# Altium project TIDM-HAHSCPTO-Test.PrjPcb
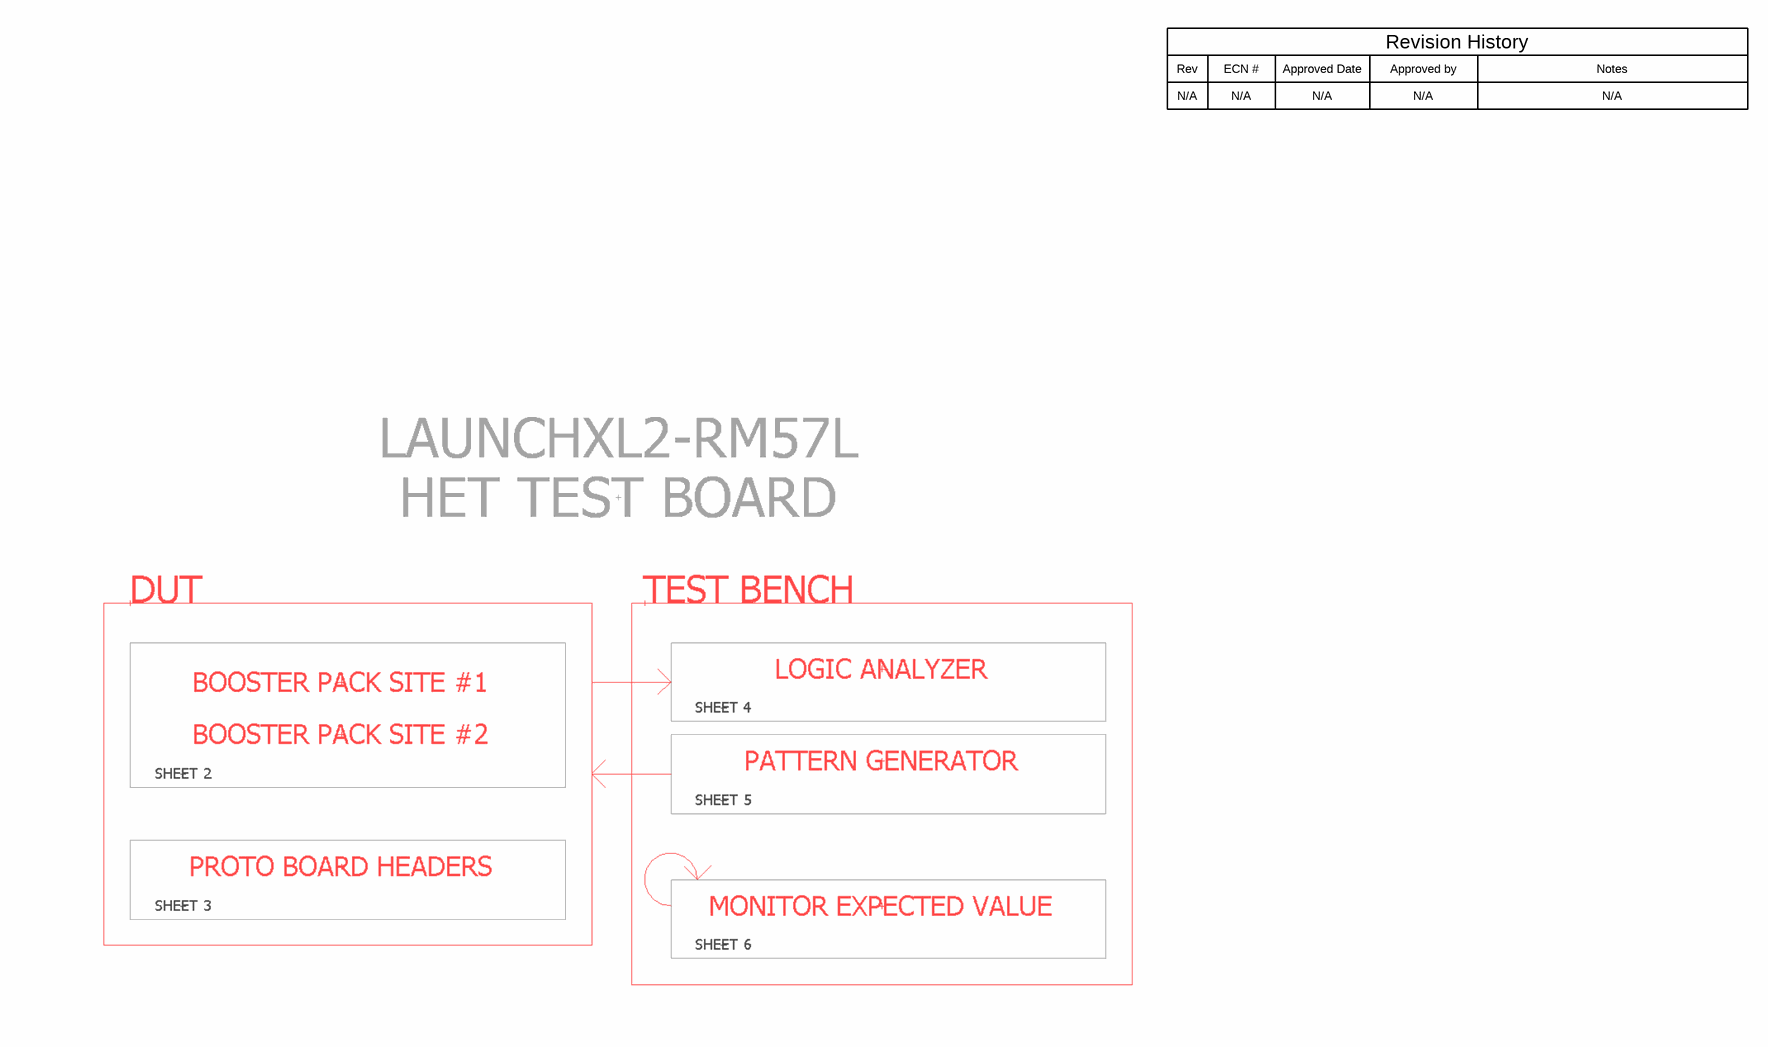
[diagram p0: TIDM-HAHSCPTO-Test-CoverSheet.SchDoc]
TID: TIDM-HAHSCPTO; TechSupport: http://www.ti.com/support; SCH_Rev: A; PRJ_Title: Test Board for TIDM-HAHSCPTO; PRJ_Number: TIDM-HAHSCPTO; PRJ_Engineer: Anthony Seely; PRJ_Customer: Public Release; PCB_Rev: A; PCB_Layout: Anthony Seely; EVM_orderable: n/a; CopyrightYear: 2016
7 sheets, 38 parts. Net scope: flat (ports and power ports of the same name join across sheets).
Board file: TIDM-HAHSCPTO-Test_PCB.PcbDoc
Sheets:
  TIDM-HAHSCPTO-Test-CoverSheet.SchDoc
  TIDM-HAHSCPTO-Test_BoosterPack.SchDoc
  TIDM-HAHSCPTO-Test_Proto.SchDoc
  TIDM-HAHSCPTO-Test_LogicAna.SchDoc
  TIDM-HAHSCPTO-Test_PatGen.SchDoc
  TIDM-HAHSCPTO-Test_Monitor.SchDoc
  TIDM-HAHSCPTO-Test_Hw.SchDoc

## Sheet TIDM-HAHSCPTO-Test-CoverSheet.SchDoc: Block Diagram
size 431 x 279 mm; Date: Not shown in title block; ApprovedBy: Not shown in title block; CheckedBy: Not shown in title block; Author: Not shown in title block; CompanyName: Not shown in title block; DrawnBy: Anthony Seely; Engineer: Anthony Seely; Organization: Not shown in title block; Address1: Not shown in title block; Address2: Not shown in title block; Address3: Not shown in title block; Address4: Not shown in title block; DocumentNumber: 1; Revision: Use project parameter SCH_Rev; SheetNumber: 1; SheetTotal: 3; PageSetup: Record=PageOptions¦CenterHorizontal=True¦CenterVertical=True¦PrintScale=1.00¦XCorrection=1.00¦YCorrection=1.00¦PrintKind=0¦BorderSize=5000000¦LeftOffset=0¦BottomOffset=0¦Orientation=2¦PaperLength=1000¦PaperWidth=1000¦Scale=100¦PaperSource=15¦PrintQuality=600¦MediaType=1¦DitherType=10¦PaperKind=Letter¦PrintScaleMode=1

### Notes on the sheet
- Rev
- N/A
- ECN #
- Approved Date
- Approved by
- Revision History
- Notes

## Sheet TIDM-HAHSCPTO-Test_BoosterPack.SchDoc: Booster Pack
size 431 x 279 mm; Date: Not shown in title block; ApprovedBy: Not shown in title block; CheckedBy: Not shown in title block; Author: Not shown in title block; CompanyName: Not shown in title block; DrawnBy: Anthony Seely; Engineer: Anthony Seely; Organization: Not shown in title block; Address1: Not shown in title block; Address2: Not shown in title block; Address3: Not shown in title block; Address4: Not shown in title block; DocumentNumber: 1; Revision: Use project parameter SCH_Rev; SheetNumber: 2; SheetTotal: 3; PageSetup: Record=PageOptions¦CenterHorizontal=True¦CenterVertical=True¦PrintScale=1.00¦XCorrection=1.00¦YCorrection=1.00¦PrintKind=0¦BorderSize=5000000¦LeftOffset=0¦BottomOffset=0¦Orientation=2¦PaperLength=1000¦PaperWidth=1000¦Scale=100¦PaperSource=15¦PrintQuality=600¦MediaType=1¦DitherType=10¦PaperKind=Letter¦PrintScaleMode=1
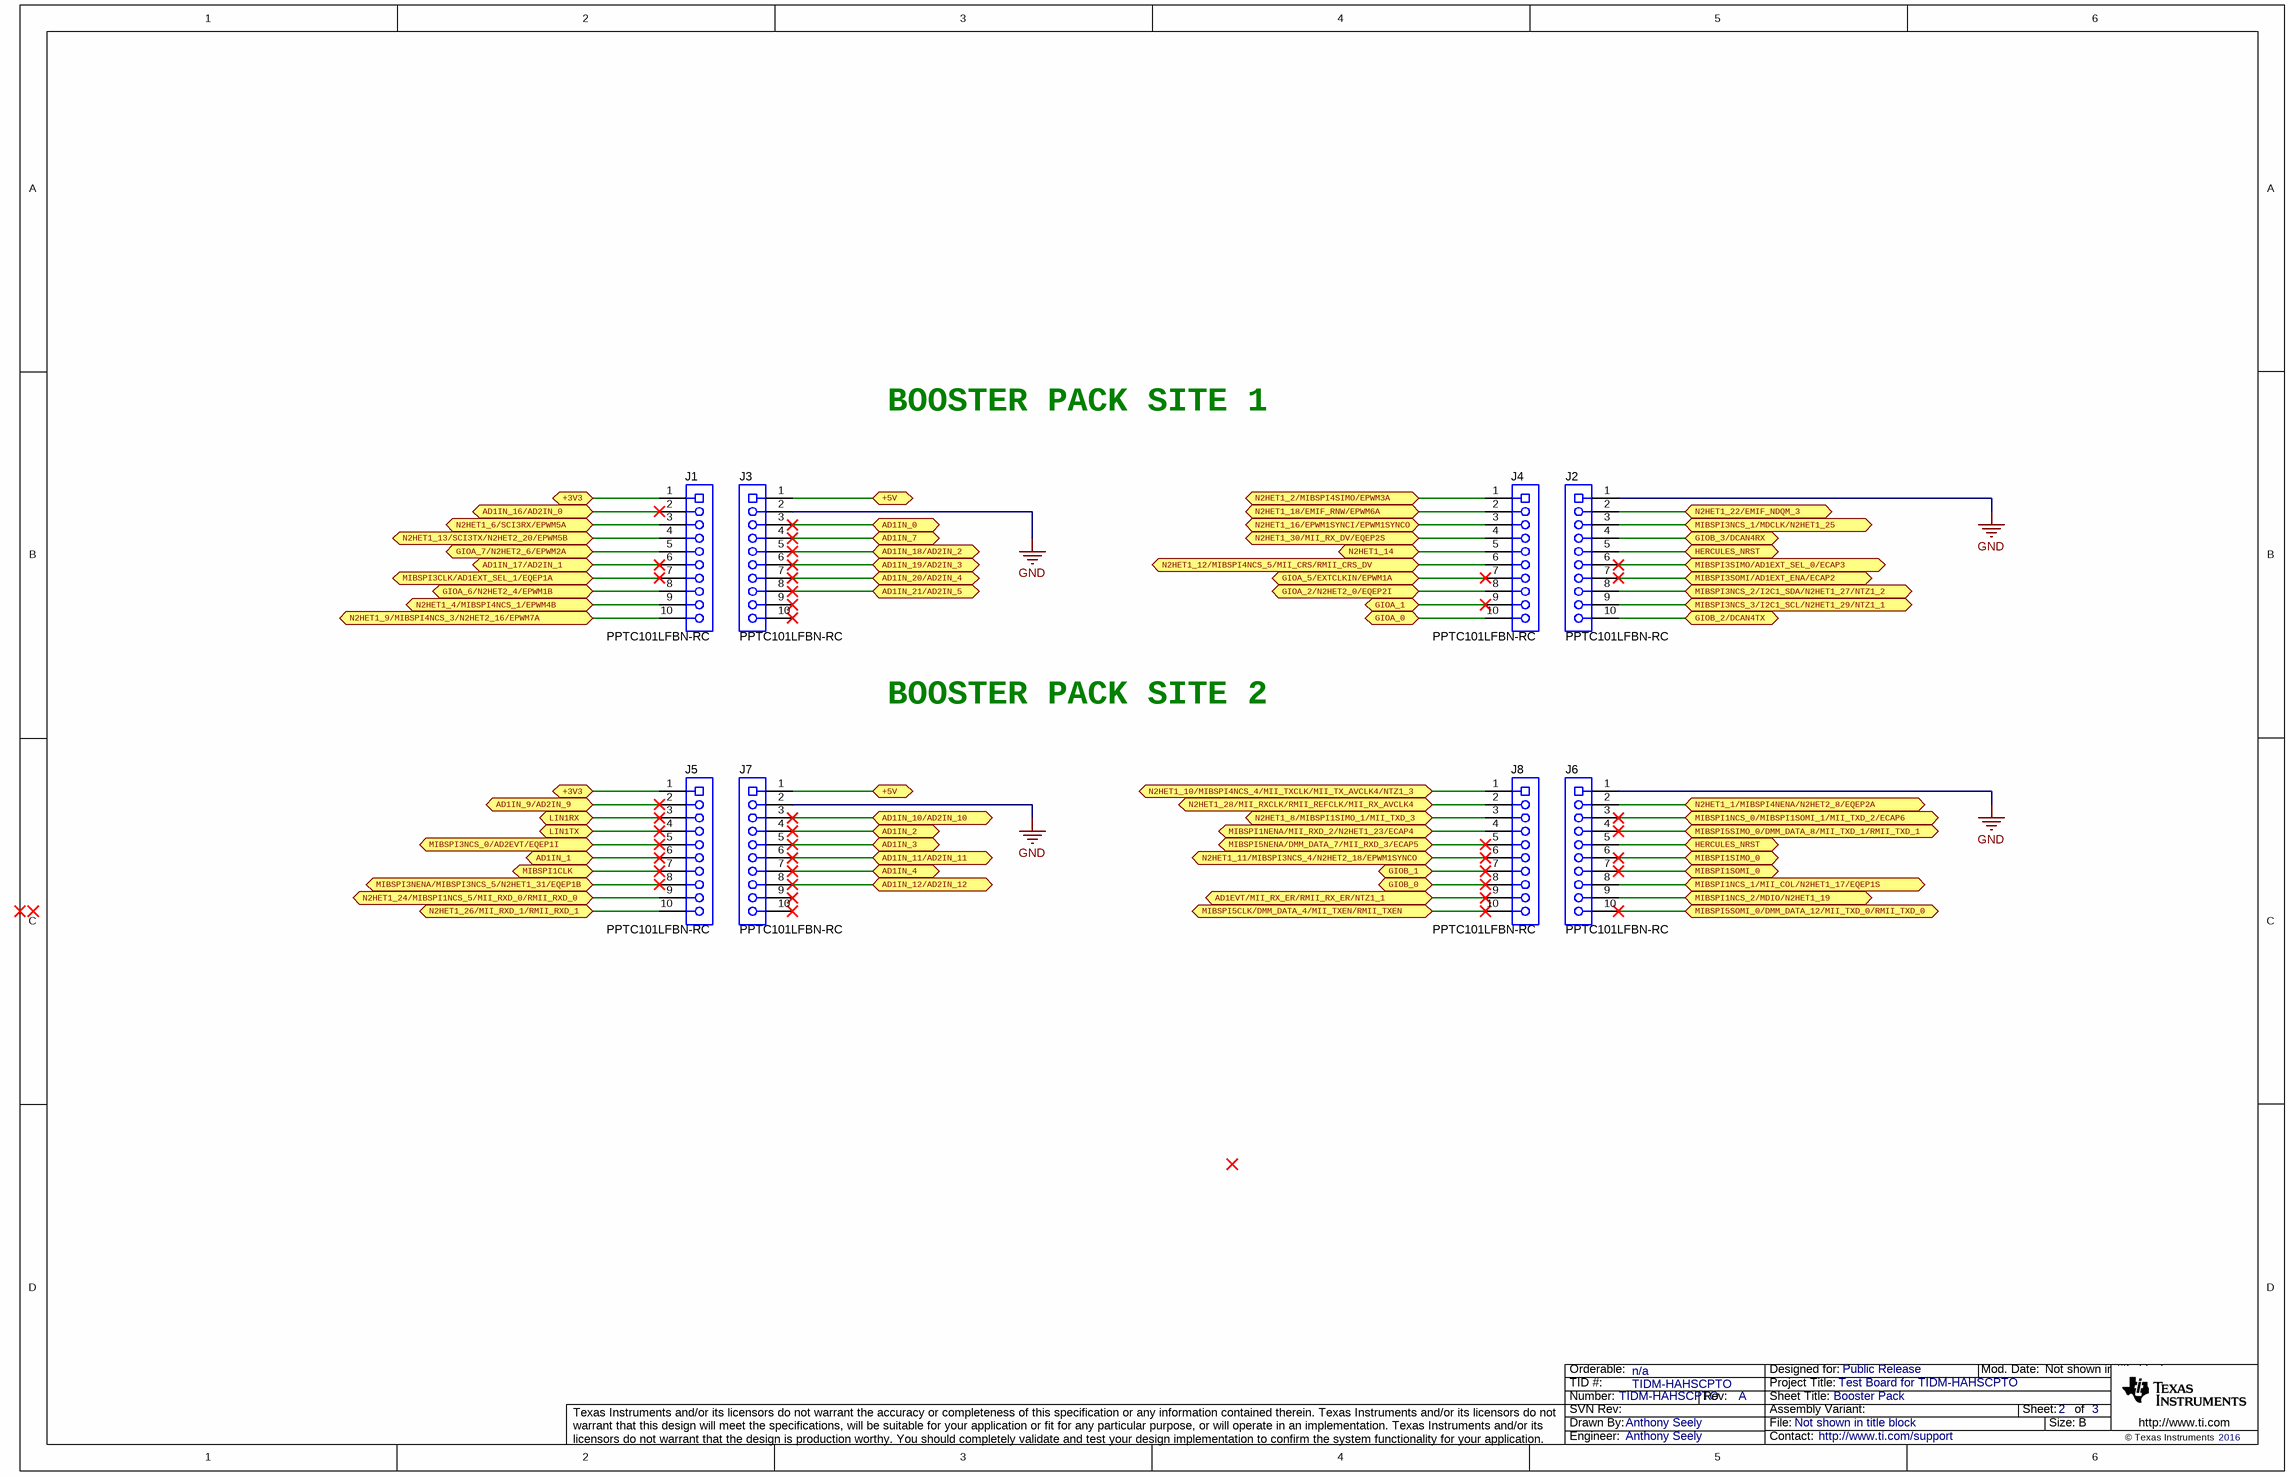
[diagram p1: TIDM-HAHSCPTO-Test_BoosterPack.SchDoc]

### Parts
J1  PPTC101LFBN-RC  [CONN_PPTC101LFBN-RC]
J2  PPTC101LFBN-RC  [CONN_PPTC101LFBN-RC]
J3  PPTC101LFBN-RC  [CONN_PPTC101LFBN-RC]
J4  PPTC101LFBN-RC  [CONN_PPTC101LFBN-RC]
J5  PPTC101LFBN-RC  [CONN_PPTC101LFBN-RC]
J6  PPTC101LFBN-RC  [CONN_PPTC101LFBN-RC]
J7  PPTC101LFBN-RC  [CONN_PPTC101LFBN-RC]
J8  PPTC101LFBN-RC  [CONN_PPTC101LFBN-RC]

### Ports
+3V3, +5V, AD1EVT/MII_RX_ER/RMII_RX_ER/NTZ1_1, AD1IN_0, AD1IN_1, AD1IN_2, AD1IN_3, AD1IN_4, AD1IN_7, AD1IN_9/AD2IN_9, AD1IN_10/AD2IN_10, AD1IN_11/AD2IN_11, AD1IN_12/AD2IN_12, AD1IN_16/AD2IN_0, AD1IN_17/AD2IN_1, AD1IN_18/AD2IN_2, AD1IN_19/AD2IN_3, AD1IN_20/AD2IN_4, AD1IN_21/AD2IN_5, GIOA_0, GIOA_1, GIOA_2/N2HET2_0/EQEP2I, GIOA_5/EXTCLKIN/EPWM1A, GIOA_6/N2HET2_4/EPWM1B, GIOA_7/N2HET2_6/EPWM2A, GIOB_0, GIOB_1, GIOB_2/DCAN4TX, GIOB_3/DCAN4RX, HERCULES_NRST, LIN1RX, LIN1TX, MIBSPI1CLK, MIBSPI1NCS_0/MIBSPI1SOMI_1/MII_TXD_2/ECAP6, MIBSPI1NCS_1/MII_COL/N2HET1_17/EQEP1S, MIBSPI1NCS_2/MDIO/N2HET1_19, MIBSPI1NENA/MII_RXD_2/N2HET1_23/ECAP4, MIBSPI1SIMO_0, MIBSPI1SOMI_0, MIBSPI3CLK/AD1EXT_SEL_1/EQEP1A, MIBSPI3NCS_0/AD2EVT/EQEP1I, MIBSPI3NCS_1/MDCLK/N2HET1_25, MIBSPI3NCS_2/I2C1_SDA/N2HET1_27/NTZ1_2, MIBSPI3NCS_3/I2C1_SCL/N2HET1_29/NTZ1_1, MIBSPI3NENA/MIBSPI3NCS_5/N2HET1_31/EQEP1B, MIBSPI3SIMO/AD1EXT_SEL_0/ECAP3, MIBSPI3SOMI/AD1EXT_ENA/ECAP2, MIBSPI5CLK/DMM_DATA_4/MII_TXEN/RMII_TXEN, MIBSPI5NENA/DMM_DATA_7/MII_RXD_3/ECAP5, MIBSPI5SIMO_0/DMM_DATA_8/MII_TXD_1/RMII_TXD_1, MIBSPI5SOMI_0/DMM_DATA_12/MII_TXD_0/RMII_TXD_0, N2HET1_1/MIBSPI4NENA/N2HET2_8/EQEP2A, N2HET1_2/MIBSPI4SIMO/EPWM3A, N2HET1_4/MIBSPI4NCS_1/EPWM4B, N2HET1_6/SCI3RX/EPWM5A, N2HET1_8/MIBSPI1SIMO_1/MII_TXD_3, N2HET1_9/MIBSPI4NCS_3/N2HET2_16/EPWM7A, N2HET1_10/MIBSPI4NCS_4/MII_TXCLK/MII_TX_AVCLK4/NTZ1_3, N2HET1_11/MIBSPI3NCS_4/N2HET2_18/EPWM1SYNCO, N2HET1_12/MIBSPI4NCS_5/MII_CRS/RMII_CRS_DV, N2HET1_13/SCI3TX/N2HET2_20/EPWM5B, N2HET1_14, N2HET1_16/EPWM1SYNCI/EPWM1SYNCO, N2HET1_18/EMIF_RNW/EPWM6A, N2HET1_22/EMIF_NDQM_3, N2HET1_24/MIBSPI1NCS_5/MII_RXD_0/RMII_RXD_0, N2HET1_26/MII_RXD_1/RMII_RXD_1, N2HET1_28/MII_RXCLK/RMII_REFCLK/MII_RX_AVCLK4, N2HET1_30/MII_RX_DV/EQEP2S

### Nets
GND: J2.1 J3.2 J6.1 J7.2
+3V3: J1.1 J5.1 ; port +3V3
+5V: J3.1 J7.1 ; port +5V
AD1EVT/MII_RX_ER/RMII_RX_ER/NTZ1_1: J8.9 ; port AD1EVT/MII_RX_ER/RMII_RX_ER/NTZ1_1
AD1IN_0: J3.3 ; port AD1IN_0
AD1IN_1: J5.6 ; port AD1IN_1
AD1IN_2: J7.4 ; port AD1IN_2
AD1IN_3: J7.5 ; port AD1IN_3
AD1IN_4: J7.7 ; port AD1IN_4
AD1IN_7: J3.4 ; port AD1IN_7
AD1IN_9/AD2IN_9: J5.2 ; port AD1IN_9/AD2IN_9
AD1IN_10/AD2IN_10: J7.3 ; port AD1IN_10/AD2IN_10
AD1IN_11/AD2IN_11: J7.6 ; port AD1IN_11/AD2IN_11
AD1IN_12/AD2IN_12: J7.8 ; port AD1IN_12/AD2IN_12
AD1IN_16/AD2IN_0: J1.2 ; port AD1IN_16/AD2IN_0
AD1IN_17/AD2IN_1: J1.6 ; port AD1IN_17/AD2IN_1
AD1IN_18/AD2IN_2: J3.5 ; port AD1IN_18/AD2IN_2
AD1IN_19/AD2IN_3: J3.6 ; port AD1IN_19/AD2IN_3
AD1IN_20/AD2IN_4: J3.7 ; port AD1IN_20/AD2IN_4
AD1IN_21/AD2IN_5: J3.8 ; port AD1IN_21/AD2IN_5
GIOA_0: J4.10 ; port GIOA_0
GIOA_1: J4.9 ; port GIOA_1
GIOA_2/N2HET2_0/EQEP2I: J4.8 ; port GIOA_2/N2HET2_0/EQEP2I
GIOA_5/EXTCLKIN/EPWM1A: J4.7 ; port GIOA_5/EXTCLKIN/EPWM1A
GIOA_6/N2HET2_4/EPWM1B: J1.8 ; port GIOA_6/N2HET2_4/EPWM1B
GIOA_7/N2HET2_6/EPWM2A: J1.5 ; port GIOA_7/N2HET2_6/EPWM2A
GIOB_0: J8.8 ; port GIOB_0
GIOB_1: J8.7 ; port GIOB_1
GIOB_2/DCAN4TX: J2.10 ; port GIOB_2/DCAN4TX
GIOB_3/DCAN4RX: J2.4 ; port GIOB_3/DCAN4RX
HERCULES_NRST: J2.5 J6.5 ; port HERCULES_NRST
LIN1RX: J5.3 ; port LIN1RX
LIN1TX: J5.4 ; port LIN1TX
MIBSPI1CLK: J5.7 ; port MIBSPI1CLK
MIBSPI1NCS_0/MIBSPI1SOMI_1/MII_TXD_2/ECAP6: J6.3 ; port MIBSPI1NCS_0/MIBSPI1SOMI_1/MII_TXD_2/ECAP6
MIBSPI1NCS_1/MII_COL/N2HET1_17/EQEP1S: J6.8 ; port MIBSPI1NCS_1/MII_COL/N2HET1_17/EQEP1S
MIBSPI1NCS_2/MDIO/N2HET1_19: J6.9 ; port MIBSPI1NCS_2/MDIO/N2HET1_19
MIBSPI1NENA/MII_RXD_2/N2HET1_23/ECAP4: J8.4 ; port MIBSPI1NENA/MII_RXD_2/N2HET1_23/ECAP4
MIBSPI1SIMO_0: J6.6 ; port MIBSPI1SIMO_0
MIBSPI1SOMI_0: J6.7 ; port MIBSPI1SOMI_0
MIBSPI3CLK/AD1EXT_SEL_1/EQEP1A: J1.7 ; port MIBSPI3CLK/AD1EXT_SEL_1/EQEP1A
MIBSPI3NCS_0/AD2EVT/EQEP1I: J5.5 ; port MIBSPI3NCS_0/AD2EVT/EQEP1I
MIBSPI3NCS_1/MDCLK/N2HET1_25: J2.3 ; port MIBSPI3NCS_1/MDCLK/N2HET1_25
MIBSPI3NCS_2/I2C1_SDA/N2HET1_27/NTZ1_2: J2.8 ; port MIBSPI3NCS_2/I2C1_SDA/N2HET1_27/NTZ1_2
MIBSPI3NCS_3/I2C1_SCL/N2HET1_29/NTZ1_1: J2.9 ; port MIBSPI3NCS_3/I2C1_SCL/N2HET1_29/NTZ1_1
MIBSPI3NENA/MIBSPI3NCS_5/N2HET1_31/EQEP1B: J5.8 ; port MIBSPI3NENA/MIBSPI3NCS_5/N2HET1_31/EQEP1B
MIBSPI3SIMO/AD1EXT_SEL_0/ECAP3: J2.6 ; port MIBSPI3SIMO/AD1EXT_SEL_0/ECAP3
MIBSPI3SOMI/AD1EXT_ENA/ECAP2: J2.7 ; port MIBSPI3SOMI/AD1EXT_ENA/ECAP2
MIBSPI5CLK/DMM_DATA_4/MII_TXEN/RMII_TXEN: J8.10 ; port MIBSPI5CLK/DMM_DATA_4/MII_TXEN/RMII_TXEN
MIBSPI5NENA/DMM_DATA_7/MII_RXD_3/ECAP5: J8.5 ; port MIBSPI5NENA/DMM_DATA_7/MII_RXD_3/ECAP5
MIBSPI5SIMO_0/DMM_DATA_8/MII_TXD_1/RMII_TXD_1: J6.4 ; port MIBSPI5SIMO_0/DMM_DATA_8/MII_TXD_1/RMII_TXD_1
MIBSPI5SOMI_0/DMM_DATA_12/MII_TXD_0/RMII_TXD_0: J6.10 ; port MIBSPI5SOMI_0/DMM_DATA_12/MII_TXD_0/RMII_TXD_0
N2HET1_1/MIBSPI4NENA/N2HET2_8/EQEP2A: J6.2 ; port N2HET1_1/MIBSPI4NENA/N2HET2_8/EQEP2A
N2HET1_2/MIBSPI4SIMO/EPWM3A: J4.1 ; port N2HET1_2/MIBSPI4SIMO/EPWM3A
N2HET1_4/MIBSPI4NCS_1/EPWM4B: J1.9 ; port N2HET1_4/MIBSPI4NCS_1/EPWM4B
N2HET1_6/SCI3RX/EPWM5A: J1.3 ; port N2HET1_6/SCI3RX/EPWM5A
N2HET1_8/MIBSPI1SIMO_1/MII_TXD_3: J8.3 ; port N2HET1_8/MIBSPI1SIMO_1/MII_TXD_3
N2HET1_9/MIBSPI4NCS_3/N2HET2_16/EPWM7A: J1.10 ; port N2HET1_9/MIBSPI4NCS_3/N2HET2_16/EPWM7A
N2HET1_10/MIBSPI4NCS_4/MII_TXCLK/MII_TX_AVCLK4/NTZ1_3: J8.1 ; port N2HET1_10/MIBSPI4NCS_4/MII_TXCLK/MII_TX_AVCLK4/NTZ1_3
N2HET1_11/MIBSPI3NCS_4/N2HET2_18/EPWM1SYNCO: J8.6 ; port N2HET1_11/MIBSPI3NCS_4/N2HET2_18/EPWM1SYNCO
N2HET1_12/MIBSPI4NCS_5/MII_CRS/RMII_CRS_DV: J4.6 ; port N2HET1_12/MIBSPI4NCS_5/MII_CRS/RMII_CRS_DV
N2HET1_13/SCI3TX/N2HET2_20/EPWM5B: J1.4 ; port N2HET1_13/SCI3TX/N2HET2_20/EPWM5B
N2HET1_14: J4.5 ; port N2HET1_14
N2HET1_16/EPWM1SYNCI/EPWM1SYNCO: J4.3 ; port N2HET1_16/EPWM1SYNCI/EPWM1SYNCO
N2HET1_18/EMIF_RNW/EPWM6A: J4.2 ; port N2HET1_18/EMIF_RNW/EPWM6A
N2HET1_22/EMIF_NDQM_3: J2.2 ; port N2HET1_22/EMIF_NDQM_3
N2HET1_24/MIBSPI1NCS_5/MII_RXD_0/RMII_RXD_0: J5.9 ; port N2HET1_24/MIBSPI1NCS_5/MII_RXD_0/RMII_RXD_0
N2HET1_26/MII_RXD_1/RMII_RXD_1: J5.10 ; port N2HET1_26/MII_RXD_1/RMII_RXD_1
N2HET1_28/MII_RXCLK/RMII_REFCLK/MII_RX_AVCLK4: J8.2 ; port N2HET1_28/MII_RXCLK/RMII_REFCLK/MII_RX_AVCLK4
N2HET1_30/MII_RX_DV/EQEP2S: J4.4 ; port N2HET1_30/MII_RX_DV/EQEP2S

Not connected (* = marked no-connect by the designer): J3 9* 10*; J7 9* 10*

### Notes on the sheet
- BOOSTER PACK SITE 1
- BOOSTER PACK SITE 2

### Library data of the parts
J1-J8 = PPTC101LFBN-RC: Receptacle, 100mil, 10x1, Tin, TH; Manufacturer: Sullins Connector Solutions; SymbolCreator: a0411947

## Sheet TIDM-HAHSCPTO-Test_Proto.SchDoc: Prototype Headers
size 431 x 279 mm; Date: Not shown in title block; ApprovedBy: Not shown in title block; CheckedBy: Not shown in title block; Author: Not shown in title block; CompanyName: Not shown in title block; DrawnBy: Anthony Seely; Engineer: Anthony Seely; Organization: Not shown in title block; Address1: Not shown in title block; Address2: Not shown in title block; Address3: Not shown in title block; Address4: Not shown in title block; DocumentNumber: 1; Revision: Use project parameter SCH_Rev; SheetNumber: 2; SheetTotal: 3; PageSetup: Record=PageOptions¦CenterHorizontal=True¦CenterVertical=True¦PrintScale=1.00¦XCorrection=1.00¦YCorrection=1.00¦PrintKind=0¦BorderSize=5000000¦LeftOffset=0¦BottomOffset=0¦Orientation=2¦PaperLength=1000¦PaperWidth=1000¦Scale=100¦PaperSource=15¦PrintQuality=600¦MediaType=1¦DitherType=10¦PaperKind=Letter¦PrintScaleMode=1
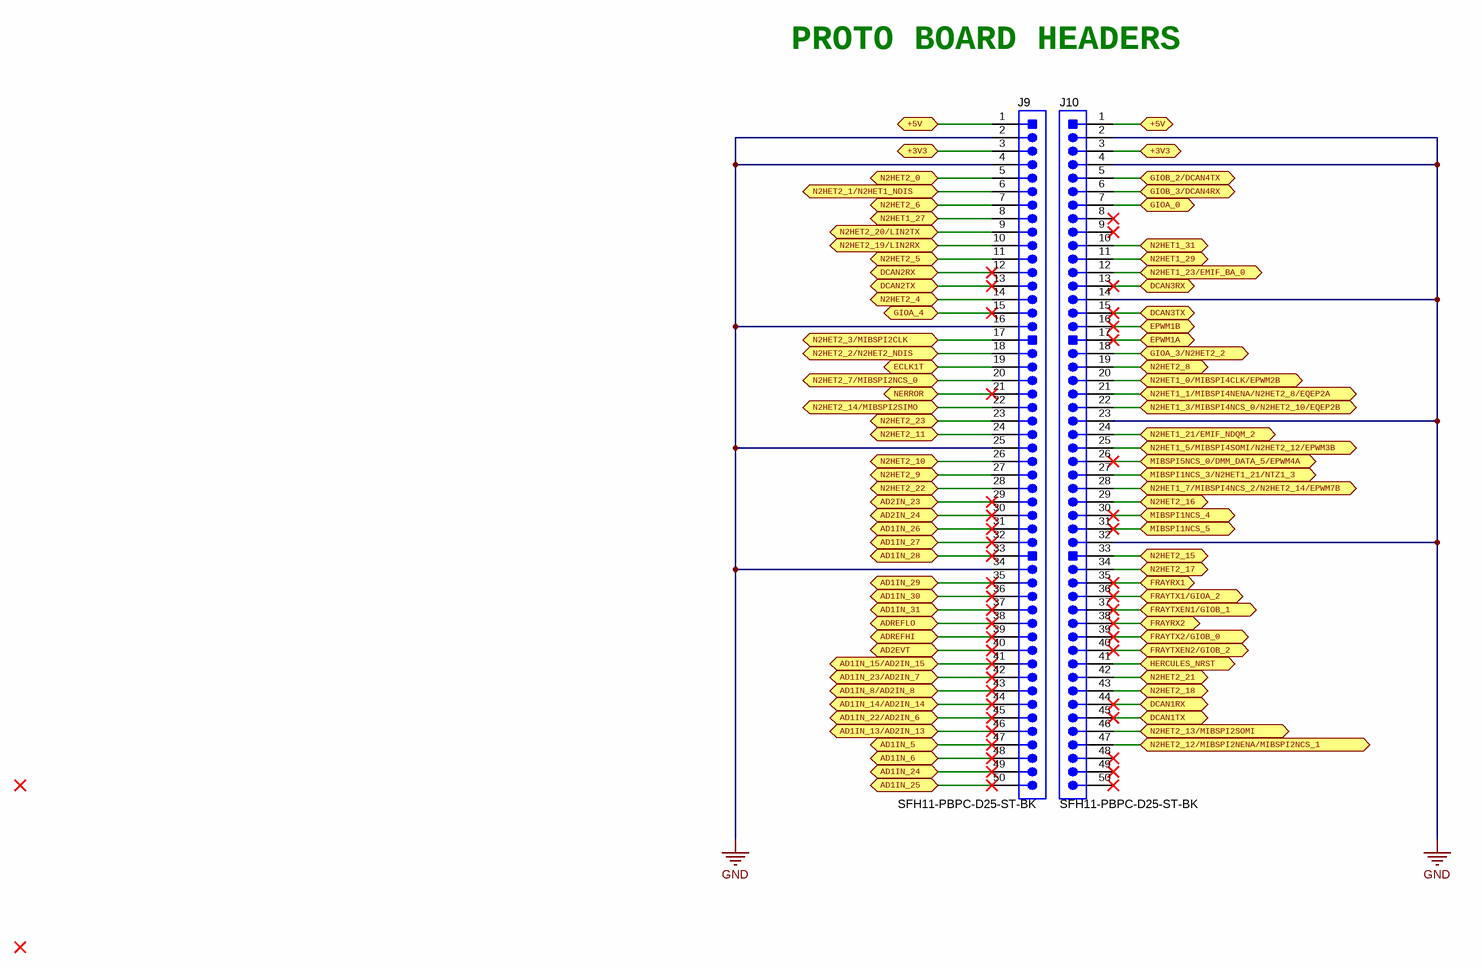
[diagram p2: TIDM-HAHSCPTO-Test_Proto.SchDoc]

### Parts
J9  SFH11-PBPC-D25-ST-BK  [SFH11-PBPC-D25-ST-BK]
J10  SFH11-PBPC-D25-ST-BK  [SFH11-PBPC-D25-ST-BK]

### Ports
+3V3, +5V, AD1IN_5, AD1IN_6, AD1IN_8/AD2IN_8, AD1IN_13/AD2IN_13, AD1IN_14/AD2IN_14, AD1IN_15/AD2IN_15, AD1IN_22/AD2IN_6, AD1IN_23/AD2IN_7, AD1IN_24, AD1IN_25, AD1IN_26, AD1IN_27, AD1IN_28, AD1IN_29, AD1IN_30, AD1IN_31, AD2EVT, AD2IN_23, AD2IN_24, ADREFHI, ADREFLO, DCAN1RX, DCAN1TX, DCAN2RX, DCAN2TX, DCAN3RX, DCAN3TX, ECLK1T, EPWM1A, EPWM1B, FRAYRX1, FRAYRX2, FRAYTX1/GIOA_2, FRAYTX2/GIOB_0, FRAYTXEN1/GIOB_1, FRAYTXEN2/GIOB_2, GIOA_0, GIOA_3/N2HET2_2, GIOA_4, GIOB_2/DCAN4TX, GIOB_3/DCAN4RX, HERCULES_NRST, MIBSPI1NCS_3/N2HET1_21/NTZ1_3, MIBSPI1NCS_4, MIBSPI1NCS_5, MIBSPI5NCS_0/DMM_DATA_5/EPWM4A, N2HET1_0/MIBSPI4CLK/EPWM2B, N2HET1_1/MIBSPI4NENA/N2HET2_8/EQEP2A, N2HET1_3/MIBSPI4NCS_0/N2HET2_10/EQEP2B, N2HET1_5/MIBSPI4SOMI/N2HET2_12/EPWM3B, N2HET1_7/MIBSPI4NCS_2/N2HET2_14/EPWM7B, N2HET1_21/EMIF_NDQM_2, N2HET1_23/EMIF_BA_0, N2HET1_27, N2HET1_29, N2HET1_31, N2HET2_0, N2HET2_1/N2HET1_NDIS, N2HET2_2/N2HET2_NDIS, N2HET2_3/MIBSPI2CLK, N2HET2_4, N2HET2_5, N2HET2_6, N2HET2_7/MIBSPI2NCS_0, N2HET2_8, N2HET2_9, N2HET2_10, N2HET2_11, N2HET2_12/MIBSPI2NENA/MIBSPI2NCS_1, N2HET2_13/MIBSPI2SOMI, N2HET2_14/MIBSPI2SIMO, N2HET2_15, N2HET2_16, N2HET2_17, N2HET2_18, N2HET2_19/LIN2RX, N2HET2_20/LIN2TX, N2HET2_21, N2HET2_22, N2HET2_23, NERROR

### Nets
GND: J9.2 J9.4 J9.16 J9.25 J9.34 J10.2 J10.4 J10.14 J10.23 J10.32
+3V3: J9.3 J10.3 ; port +3V3
+5V: J9.1 J10.1 ; port +5V
AD1IN_5: J9.47 ; port AD1IN_5
AD1IN_6: J9.48 ; port AD1IN_6
AD1IN_8/AD2IN_8: J9.43 ; port AD1IN_8/AD2IN_8
AD1IN_13/AD2IN_13: J9.46 ; port AD1IN_13/AD2IN_13
AD1IN_14/AD2IN_14: J9.44 ; port AD1IN_14/AD2IN_14
AD1IN_15/AD2IN_15: J9.41 ; port AD1IN_15/AD2IN_15
AD1IN_22/AD2IN_6: J9.45 ; port AD1IN_22/AD2IN_6
AD1IN_23/AD2IN_7: J9.42 ; port AD1IN_23/AD2IN_7
AD1IN_24: J9.49 ; port AD1IN_24
AD1IN_25: J9.50 ; port AD1IN_25
AD1IN_26: J9.31 ; port AD1IN_26
AD1IN_27: J9.32 ; port AD1IN_27
AD1IN_28: J9.33 ; port AD1IN_28
AD1IN_29: J9.35 ; port AD1IN_29
AD1IN_30: J9.36 ; port AD1IN_30
AD1IN_31: J9.37 ; port AD1IN_31
AD2EVT: J9.40 ; port AD2EVT
AD2IN_23: J9.29 ; port AD2IN_23
AD2IN_24: J9.30 ; port AD2IN_24
ADREFHI: J9.39 ; port ADREFHI
ADREFLO: J9.38 ; port ADREFLO
DCAN1RX: J10.44 ; port DCAN1RX
DCAN1TX: J10.45 ; port DCAN1TX
DCAN2RX: J9.12 ; port DCAN2RX
DCAN2TX: J9.13 ; port DCAN2TX
DCAN3RX: J10.13 ; port DCAN3RX
DCAN3TX: J10.15 ; port DCAN3TX
ECLK1T: J9.19 ; port ECLK1T
EPWM1A: J10.17 ; port EPWM1A
EPWM1B: J10.16 ; port EPWM1B
FRAYRX1: J10.35 ; port FRAYRX1
FRAYRX2: J10.38 ; port FRAYRX2
FRAYTX1/GIOA_2: J10.36 ; port FRAYTX1/GIOA_2
FRAYTX2/GIOB_0: J10.39 ; port FRAYTX2/GIOB_0
FRAYTXEN1/GIOB_1: J10.37 ; port FRAYTXEN1/GIOB_1
FRAYTXEN2/GIOB_2: J10.40 ; port FRAYTXEN2/GIOB_2
GIOA_0: J10.7 ; port GIOA_0
GIOA_3/N2HET2_2: J10.18 ; port GIOA_3/N2HET2_2
GIOA_4: J9.15 ; port GIOA_4
GIOB_2/DCAN4TX: J10.5 ; port GIOB_2/DCAN4TX
GIOB_3/DCAN4RX: J10.6 ; port GIOB_3/DCAN4RX
HERCULES_NRST: J10.41 ; port HERCULES_NRST
MIBSPI1NCS_3/N2HET1_21/NTZ1_3: J10.27 ; port MIBSPI1NCS_3/N2HET1_21/NTZ1_3
MIBSPI1NCS_4: J10.30 ; port MIBSPI1NCS_4
MIBSPI1NCS_5: J10.31 ; port MIBSPI1NCS_5
MIBSPI5NCS_0/DMM_DATA_5/EPWM4A: J10.26 ; port MIBSPI5NCS_0/DMM_DATA_5/EPWM4A
N2HET1_0/MIBSPI4CLK/EPWM2B: J10.20 ; port N2HET1_0/MIBSPI4CLK/EPWM2B
N2HET1_1/MIBSPI4NENA/N2HET2_8/EQEP2A: J10.21 ; port N2HET1_1/MIBSPI4NENA/N2HET2_8/EQEP2A
N2HET1_3/MIBSPI4NCS_0/N2HET2_10/EQEP2B: J10.22 ; port N2HET1_3/MIBSPI4NCS_0/N2HET2_10/EQEP2B
N2HET1_5/MIBSPI4SOMI/N2HET2_12/EPWM3B: J10.25 ; port N2HET1_5/MIBSPI4SOMI/N2HET2_12/EPWM3B
N2HET1_7/MIBSPI4NCS_2/N2HET2_14/EPWM7B: J10.28 ; port N2HET1_7/MIBSPI4NCS_2/N2HET2_14/EPWM7B
N2HET1_21/EMIF_NDQM_2: J10.24 ; port N2HET1_21/EMIF_NDQM_2
N2HET1_23/EMIF_BA_0: J10.12 ; port N2HET1_23/EMIF_BA_0
N2HET1_27: J9.8 ; port N2HET1_27
N2HET1_29: J10.11 ; port N2HET1_29
N2HET1_31: J10.10 ; port N2HET1_31
N2HET2_0: J9.5 ; port N2HET2_0
N2HET2_1/N2HET1_NDIS: J9.6 ; port N2HET2_1/N2HET1_NDIS
N2HET2_2/N2HET2_NDIS: J9.18 ; port N2HET2_2/N2HET2_NDIS
N2HET2_3/MIBSPI2CLK: J9.17 ; port N2HET2_3/MIBSPI2CLK
N2HET2_4: J9.14 ; port N2HET2_4
N2HET2_5: J9.11 ; port N2HET2_5
N2HET2_6: J9.7 ; port N2HET2_6
N2HET2_7/MIBSPI2NCS_0: J9.20 ; port N2HET2_7/MIBSPI2NCS_0
N2HET2_8: J10.19 ; port N2HET2_8
N2HET2_9: J9.27 ; port N2HET2_9
N2HET2_10: J9.26 ; port N2HET2_10
N2HET2_11: J9.24 ; port N2HET2_11
N2HET2_12/MIBSPI2NENA/MIBSPI2NCS_1: J10.47 ; port N2HET2_12/MIBSPI2NENA/MIBSPI2NCS_1
N2HET2_13/MIBSPI2SOMI: J10.46 ; port N2HET2_13/MIBSPI2SOMI
N2HET2_14/MIBSPI2SIMO: J9.22 ; port N2HET2_14/MIBSPI2SIMO
N2HET2_15: J10.33 ; port N2HET2_15
N2HET2_16: J10.29 ; port N2HET2_16
N2HET2_17: J10.34 ; port N2HET2_17
N2HET2_18: J10.43 ; port N2HET2_18
N2HET2_19/LIN2RX: J9.10 ; port N2HET2_19/LIN2RX
N2HET2_20/LIN2TX: J9.9 ; port N2HET2_20/LIN2TX
N2HET2_21: J10.42 ; port N2HET2_21
N2HET2_22: J9.28 ; port N2HET2_22
N2HET2_23: J9.23 ; port N2HET2_23
NERROR: J9.21 ; port NERROR

Not connected (* = marked no-connect by the designer): J10 8* 9* 48* 49* 50*

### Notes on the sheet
- PROTO BOARD HEADERS

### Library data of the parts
J9 J10 = SFH11-PBPC-D25-ST-BK: .100" 1 Row, Thru Hole with Polarizing Key; Manufacturer: Sullins; SymbolCreator: a0321811; CompType: Connector

## Sheet TIDM-HAHSCPTO-Test_LogicAna.SchDoc: Logic Analyzer Headers
size 431 x 279 mm; Date: Not shown in title block; ApprovedBy: Not shown in title block; CheckedBy: Not shown in title block; Author: Not shown in title block; CompanyName: Not shown in title block; DrawnBy: Anthony  Seely; Engineer: Anthony Seely; Organization: Not shown in title block; Address1: Not shown in title block; Address2: Not shown in title block; Address3: Not shown in title block; Address4: Not shown in title block; DocumentNumber: 1; Revision: Use project parameter SCH_Rev; SheetNumber: 2; SheetTotal: 3; PageSetup: Record=PageOptions¦CenterHorizontal=True¦CenterVertical=True¦PrintScale=1.00¦XCorrection=1.00¦YCorrection=1.00¦PrintKind=0¦BorderSize=5000000¦LeftOffset=0¦BottomOffset=0¦Orientation=2¦PaperLength=1000¦PaperWidth=1000¦Scale=100¦PaperSource=15¦PrintQuality=600¦MediaType=1¦DitherType=10¦PaperKind=Letter¦PrintScaleMode=1
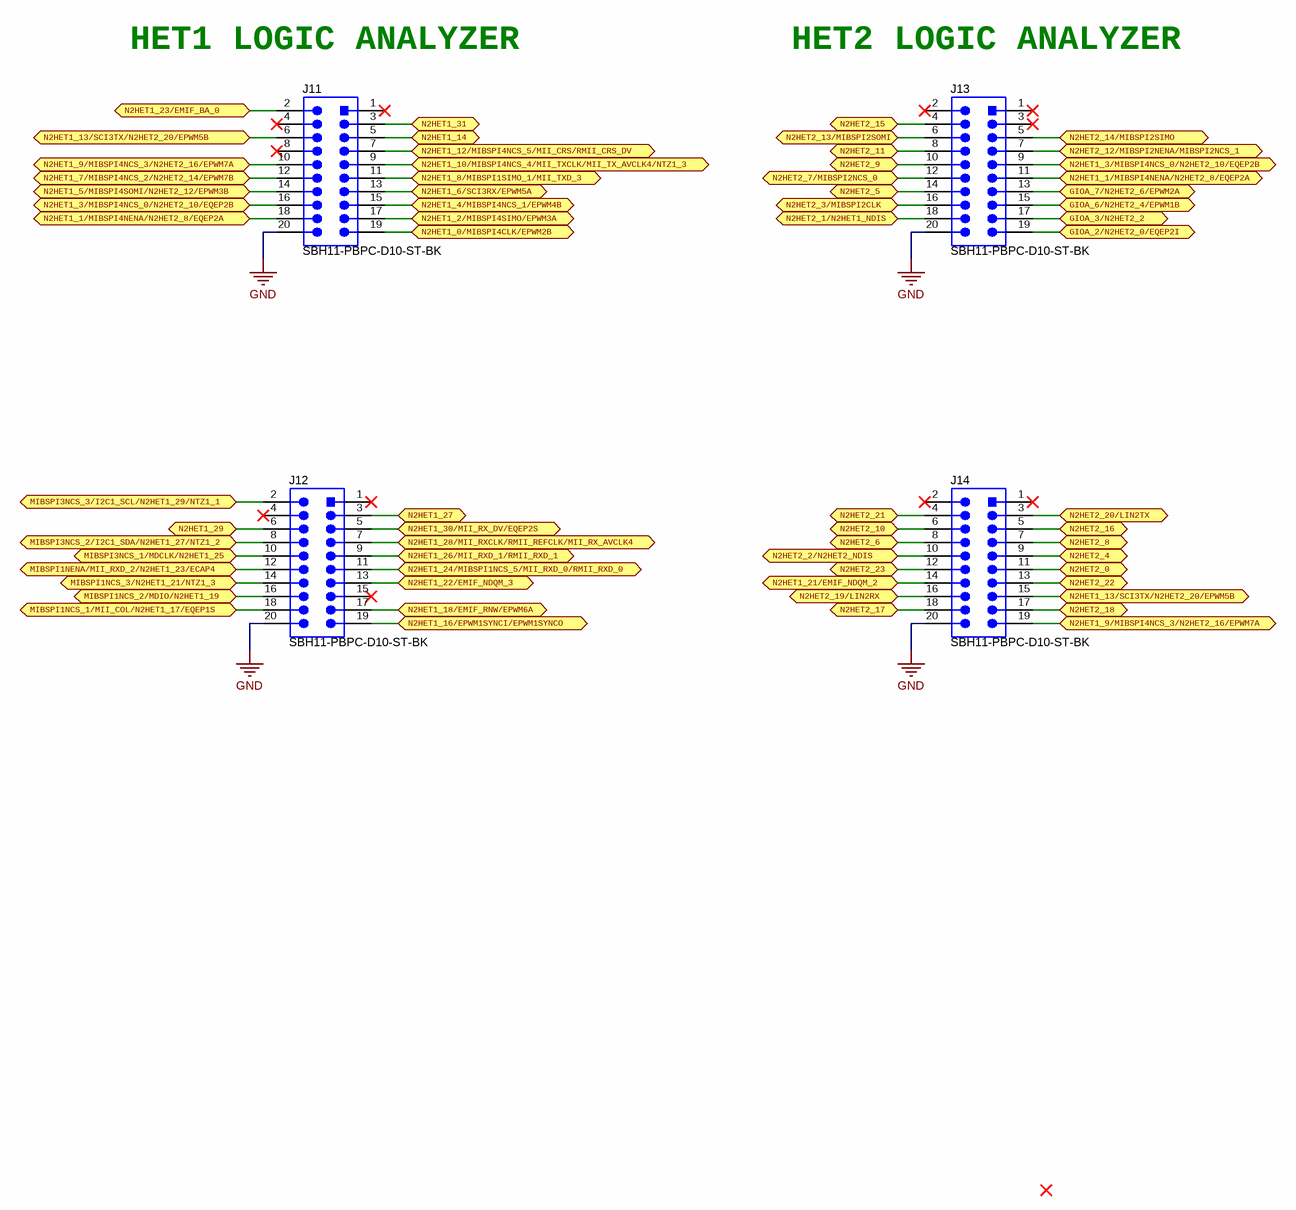
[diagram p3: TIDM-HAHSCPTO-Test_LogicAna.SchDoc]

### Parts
J11  SBH11-PBPC-D10-ST-BK  [Sullins_SBH11-xxxC-D10-ST]
J12  SBH11-PBPC-D10-ST-BK  [Sullins_SBH11-xxxC-D10-ST]
J13  SBH11-PBPC-D10-ST-BK  [Sullins_SBH11-xxxC-D10-ST]
J14  SBH11-PBPC-D10-ST-BK  [Sullins_SBH11-xxxC-D10-ST]

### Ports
GIOA_2/N2HET2_0/EQEP2I, GIOA_3/N2HET2_2, GIOA_6/N2HET2_4/EPWM1B, GIOA_7/N2HET2_6/EPWM2A, MIBSPI1NCS_1/MII_COL/N2HET1_17/EQEP1S, MIBSPI1NCS_2/MDIO/N2HET1_19, MIBSPI1NCS_3/N2HET1_21/NTZ1_3, MIBSPI1NENA/MII_RXD_2/N2HET1_23/ECAP4, MIBSPI3NCS_1/MDCLK/N2HET1_25, MIBSPI3NCS_2/I2C1_SDA/N2HET1_27/NTZ1_2, MIBSPI3NCS_3/I2C1_SCL/N2HET1_29/NTZ1_1, N2HET1_0/MIBSPI4CLK/EPWM2B, N2HET1_1/MIBSPI4NENA/N2HET2_8/EQEP2A, N2HET1_2/MIBSPI4SIMO/EPWM3A, N2HET1_3/MIBSPI4NCS_0/N2HET2_10/EQEP2B, N2HET1_4/MIBSPI4NCS_1/EPWM4B, N2HET1_5/MIBSPI4SOMI/N2HET2_12/EPWM3B, N2HET1_6/SCI3RX/EPWM5A, N2HET1_7/MIBSPI4NCS_2/N2HET2_14/EPWM7B, N2HET1_8/MIBSPI1SIMO_1/MII_TXD_3, N2HET1_9/MIBSPI4NCS_3/N2HET2_16/EPWM7A, N2HET1_10/MIBSPI4NCS_4/MII_TXCLK/MII_TX_AVCLK4/NTZ1_3, N2HET1_12/MIBSPI4NCS_5/MII_CRS/RMII_CRS_DV, N2HET1_13/SCI3TX/N2HET2_20/EPWM5B, N2HET1_14, N2HET1_16/EPWM1SYNCI/EPWM1SYNCO, N2HET1_18/EMIF_RNW/EPWM6A, N2HET1_21/EMIF_NDQM_2, N2HET1_22/EMIF_NDQM_3, N2HET1_23/EMIF_BA_0, N2HET1_24/MIBSPI1NCS_5/MII_RXD_0/RMII_RXD_0, N2HET1_26/MII_RXD_1/RMII_RXD_1, N2HET1_27, N2HET1_28/MII_RXCLK/RMII_REFCLK/MII_RX_AVCLK4, N2HET1_29, N2HET1_30/MII_RX_DV/EQEP2S, N2HET1_31, N2HET2_0, N2HET2_1/N2HET1_NDIS, N2HET2_2/N2HET2_NDIS, N2HET2_3/MIBSPI2CLK, N2HET2_4, N2HET2_5, N2HET2_6, N2HET2_7/MIBSPI2NCS_0, N2HET2_8, N2HET2_9, N2HET2_10, N2HET2_11, N2HET2_12/MIBSPI2NENA/MIBSPI2NCS_1, N2HET2_13/MIBSPI2SOMI, N2HET2_14/MIBSPI2SIMO, N2HET2_15, N2HET2_16, N2HET2_17, N2HET2_18, N2HET2_19/LIN2RX, N2HET2_20/LIN2TX, N2HET2_21, N2HET2_22, N2HET2_23

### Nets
GND: J11.20 J12.20 J13.20 J14.20
GIOA_2/N2HET2_0/EQEP2I: J13.19 ; port GIOA_2/N2HET2_0/EQEP2I
GIOA_3/N2HET2_2: J13.17 ; port GIOA_3/N2HET2_2
GIOA_6/N2HET2_4/EPWM1B: J13.15 ; port GIOA_6/N2HET2_4/EPWM1B
GIOA_7/N2HET2_6/EPWM2A: J13.13 ; port GIOA_7/N2HET2_6/EPWM2A
MIBSPI1NCS_1/MII_COL/N2HET1_17/EQEP1S: J12.18 ; port MIBSPI1NCS_1/MII_COL/N2HET1_17/EQEP1S
MIBSPI1NCS_2/MDIO/N2HET1_19: J12.16 ; port MIBSPI1NCS_2/MDIO/N2HET1_19
MIBSPI1NCS_3/N2HET1_21/NTZ1_3: J12.14 ; port MIBSPI1NCS_3/N2HET1_21/NTZ1_3
MIBSPI1NENA/MII_RXD_2/N2HET1_23/ECAP4: J12.12 ; port MIBSPI1NENA/MII_RXD_2/N2HET1_23/ECAP4
MIBSPI3NCS_1/MDCLK/N2HET1_25: J12.10 ; port MIBSPI3NCS_1/MDCLK/N2HET1_25
MIBSPI3NCS_2/I2C1_SDA/N2HET1_27/NTZ1_2: J12.8 ; port MIBSPI3NCS_2/I2C1_SDA/N2HET1_27/NTZ1_2
MIBSPI3NCS_3/I2C1_SCL/N2HET1_29/NTZ1_1: J12.2 ; port MIBSPI3NCS_3/I2C1_SCL/N2HET1_29/NTZ1_1
N2HET1_0/MIBSPI4CLK/EPWM2B: J11.19 ; port N2HET1_0/MIBSPI4CLK/EPWM2B
N2HET1_1/MIBSPI4NENA/N2HET2_8/EQEP2A: J11.18 J13.11 ; port N2HET1_1/MIBSPI4NENA/N2HET2_8/EQEP2A
N2HET1_2/MIBSPI4SIMO/EPWM3A: J11.17 ; port N2HET1_2/MIBSPI4SIMO/EPWM3A
N2HET1_3/MIBSPI4NCS_0/N2HET2_10/EQEP2B: J11.16 J13.9 ; port N2HET1_3/MIBSPI4NCS_0/N2HET2_10/EQEP2B
N2HET1_4/MIBSPI4NCS_1/EPWM4B: J11.15 ; port N2HET1_4/MIBSPI4NCS_1/EPWM4B
N2HET1_5/MIBSPI4SOMI/N2HET2_12/EPWM3B: J11.14 ; port N2HET1_5/MIBSPI4SOMI/N2HET2_12/EPWM3B
N2HET1_6/SCI3RX/EPWM5A: J11.13 ; port N2HET1_6/SCI3RX/EPWM5A
N2HET1_7/MIBSPI4NCS_2/N2HET2_14/EPWM7B: J11.12 ; port N2HET1_7/MIBSPI4NCS_2/N2HET2_14/EPWM7B
N2HET1_8/MIBSPI1SIMO_1/MII_TXD_3: J11.11 ; port N2HET1_8/MIBSPI1SIMO_1/MII_TXD_3
N2HET1_9/MIBSPI4NCS_3/N2HET2_16/EPWM7A: J11.10 J14.19 ; port N2HET1_9/MIBSPI4NCS_3/N2HET2_16/EPWM7A
N2HET1_10/MIBSPI4NCS_4/MII_TXCLK/MII_TX_AVCLK4/NTZ1_3: J11.9 ; port N2HET1_10/MIBSPI4NCS_4/MII_TXCLK/MII_TX_AVCLK4/NTZ1_3
N2HET1_12/MIBSPI4NCS_5/MII_CRS/RMII_CRS_DV: J11.7 ; port N2HET1_12/MIBSPI4NCS_5/MII_CRS/RMII_CRS_DV
N2HET1_13/SCI3TX/N2HET2_20/EPWM5B: J11.6 J14.15 ; port N2HET1_13/SCI3TX/N2HET2_20/EPWM5B
N2HET1_14: J11.5 ; port N2HET1_14
N2HET1_16/EPWM1SYNCI/EPWM1SYNCO: J12.19 ; port N2HET1_16/EPWM1SYNCI/EPWM1SYNCO
N2HET1_18/EMIF_RNW/EPWM6A: J12.17 ; port N2HET1_18/EMIF_RNW/EPWM6A
N2HET1_21/EMIF_NDQM_2: J14.14 ; port N2HET1_21/EMIF_NDQM_2
N2HET1_22/EMIF_NDQM_3: J12.13 ; port N2HET1_22/EMIF_NDQM_3
N2HET1_23/EMIF_BA_0: J11.2 ; port N2HET1_23/EMIF_BA_0
N2HET1_24/MIBSPI1NCS_5/MII_RXD_0/RMII_RXD_0: J12.11 ; port N2HET1_24/MIBSPI1NCS_5/MII_RXD_0/RMII_RXD_0
N2HET1_26/MII_RXD_1/RMII_RXD_1: J12.9 ; port N2HET1_26/MII_RXD_1/RMII_RXD_1
N2HET1_27: J12.3 ; port N2HET1_27
N2HET1_28/MII_RXCLK/RMII_REFCLK/MII_RX_AVCLK4: J12.7 ; port N2HET1_28/MII_RXCLK/RMII_REFCLK/MII_RX_AVCLK4
N2HET1_29: J12.6 ; port N2HET1_29
N2HET1_30/MII_RX_DV/EQEP2S: J12.5 ; port N2HET1_30/MII_RX_DV/EQEP2S
N2HET1_31: J11.3 ; port N2HET1_31
N2HET2_0: J14.11 ; port N2HET2_0
N2HET2_1/N2HET1_NDIS: J13.18 ; port N2HET2_1/N2HET1_NDIS
N2HET2_2/N2HET2_NDIS: J14.10 ; port N2HET2_2/N2HET2_NDIS
N2HET2_3/MIBSPI2CLK: J13.16 ; port N2HET2_3/MIBSPI2CLK
N2HET2_4: J14.9 ; port N2HET2_4
N2HET2_5: J13.14 ; port N2HET2_5
N2HET2_6: J14.8 ; port N2HET2_6
N2HET2_7/MIBSPI2NCS_0: J13.12 ; port N2HET2_7/MIBSPI2NCS_0
N2HET2_8: J14.7 ; port N2HET2_8
N2HET2_9: J13.10 ; port N2HET2_9
N2HET2_10: J14.6 ; port N2HET2_10
N2HET2_11: J13.8 ; port N2HET2_11
N2HET2_12/MIBSPI2NENA/MIBSPI2NCS_1: J13.7 ; port N2HET2_12/MIBSPI2NENA/MIBSPI2NCS_1
N2HET2_13/MIBSPI2SOMI: J13.6 ; port N2HET2_13/MIBSPI2SOMI
N2HET2_14/MIBSPI2SIMO: J13.5 ; port N2HET2_14/MIBSPI2SIMO
N2HET2_15: J13.4 ; port N2HET2_15
N2HET2_16: J14.5 ; port N2HET2_16
N2HET2_17: J14.18 ; port N2HET2_17
N2HET2_18: J14.17 ; port N2HET2_18
N2HET2_19/LIN2RX: J14.16 ; port N2HET2_19/LIN2RX
N2HET2_20/LIN2TX: J14.3 ; port N2HET2_20/LIN2TX
N2HET2_21: J14.4 ; port N2HET2_21
N2HET2_22: J14.13 ; port N2HET2_22
N2HET2_23: J14.12 ; port N2HET2_23

Not connected (* = marked no-connect by the designer): J11 1* 4* 8*; J12 1* 4* 15*; J13 1* 2* 3*; J14 1* 2*

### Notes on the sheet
- (near J11) HET1 LOGIC ANALYZER
- (near J13) HET2 LOGIC ANALYZER

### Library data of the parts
J11-J14 = SBH11-PBPC-D10-ST-BK: Header (Shrouded), 2.54mm, 10x2, Gold, Black, TH; Manufacturer: Sullins Connector Solutions; SymbolCreator: a0412235; Pitch_mm: 2.54; Gender: Male; Shrouded: Y; Row_Count: 2; Current_A: 3; Voltage_V: 1000

## Sheet TIDM-HAHSCPTO-Test_PatGen.SchDoc
size 431 x 279 mm; Date: Not shown in title block; ApprovedBy: Not shown in title block; CheckedBy: Not shown in title block; Author: Not shown in title block; CompanyName: Not shown in title block; Engineer: Not shown in title block; Organization: Not shown in title block; Address1: Not shown in title block; Address2: Not shown in title block; Address3: Not shown in title block; Address4: Not shown in title block; DocumentNumber: 1; Revision: Use project parameter SCH_Rev; SheetNumber: 2; SheetTotal: 3; PageSetup: Record=PageOptions¦CenterHorizontal=True¦CenterVertical=True¦PrintScale=1.00¦XCorrection=1.00¦YCorrection=1.00¦PrintKind=0¦BorderSize=5000000¦LeftOffset=0¦BottomOffset=0¦Orientation=2¦PaperLength=1000¦PaperWidth=1000¦Scale=100¦PaperSource=15¦PrintQuality=600¦MediaType=1¦DitherType=10¦PaperKind=Letter¦PrintScaleMode=1
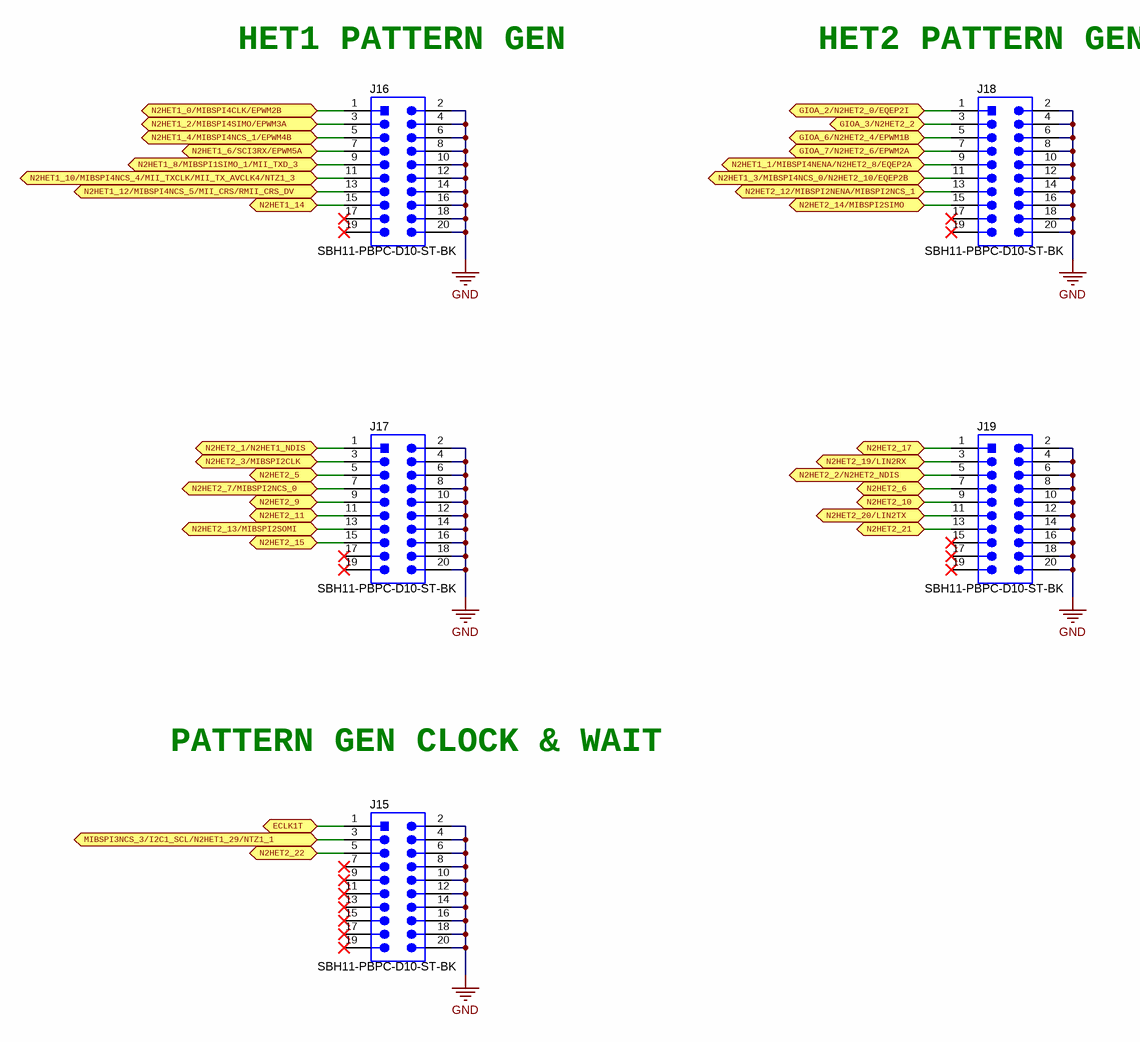
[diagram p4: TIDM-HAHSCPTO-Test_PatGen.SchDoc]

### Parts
J15  SBH11-PBPC-D10-ST-BK  [Sullins_SBH11-xxxC-D10-ST]
J16  SBH11-PBPC-D10-ST-BK  [Sullins_SBH11-xxxC-D10-ST]
J17  SBH11-PBPC-D10-ST-BK  [Sullins_SBH11-xxxC-D10-ST]
J18  SBH11-PBPC-D10-ST-BK  [Sullins_SBH11-xxxC-D10-ST]
J19  SBH11-PBPC-D10-ST-BK  [Sullins_SBH11-xxxC-D10-ST]

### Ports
ECLK1T, GIOA_2/N2HET2_0/EQEP2I, GIOA_3/N2HET2_2, GIOA_6/N2HET2_4/EPWM1B, GIOA_7/N2HET2_6/EPWM2A, MIBSPI3NCS_3/I2C1_SCL/N2HET1_29/NTZ1_1, N2HET1_0/MIBSPI4CLK/EPWM2B, N2HET1_1/MIBSPI4NENA/N2HET2_8/EQEP2A, N2HET1_2/MIBSPI4SIMO/EPWM3A, N2HET1_3/MIBSPI4NCS_0/N2HET2_10/EQEP2B, N2HET1_4/MIBSPI4NCS_1/EPWM4B, N2HET1_6/SCI3RX/EPWM5A, N2HET1_8/MIBSPI1SIMO_1/MII_TXD_3, N2HET1_10/MIBSPI4NCS_4/MII_TXCLK/MII_TX_AVCLK4/NTZ1_3, N2HET1_12/MIBSPI4NCS_5/MII_CRS/RMII_CRS_DV, N2HET1_14, N2HET2_1/N2HET1_NDIS, N2HET2_2/N2HET2_NDIS, N2HET2_3/MIBSPI2CLK, N2HET2_5, N2HET2_6, N2HET2_7/MIBSPI2NCS_0, N2HET2_9, N2HET2_10, N2HET2_11, N2HET2_12/MIBSPI2NENA/MIBSPI2NCS_1, N2HET2_13/MIBSPI2SOMI, N2HET2_14/MIBSPI2SIMO, N2HET2_15, N2HET2_17, N2HET2_19/LIN2RX, N2HET2_20/LIN2TX, N2HET2_21, N2HET2_22

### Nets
GND: J15.2 J15.4 J15.6 J15.8 J15.10 J15.12 J15.14 J15.16 J15.18 J15.20 J16.2 J16.4 J16.6 J16.8 J16.10 J16.12 J16.14 J16.16 J16.18 J16.20 J17.2 J17.4 J17.6 J17.8 J17.10 J17.12 J17.14 J17.16 J17.18 J17.20 J18.2 J18.4 J18.6 J18.8 J18.10 J18.12 J18.14 J18.16 J18.18 J18.20 J19.2 J19.4 J19.6 J19.8 J19.10 J19.12 J19.14 J19.16 J19.18 J19.20
ECLK1T: J15.1 ; port ECLK1T
GIOA_2/N2HET2_0/EQEP2I: J18.1 ; port GIOA_2/N2HET2_0/EQEP2I
GIOA_3/N2HET2_2: J18.3 ; port GIOA_3/N2HET2_2
GIOA_6/N2HET2_4/EPWM1B: J18.5 ; port GIOA_6/N2HET2_4/EPWM1B
GIOA_7/N2HET2_6/EPWM2A: J18.7 ; port GIOA_7/N2HET2_6/EPWM2A
MIBSPI3NCS_3/I2C1_SCL/N2HET1_29/NTZ1_1: J15.3 ; port MIBSPI3NCS_3/I2C1_SCL/N2HET1_29/NTZ1_1
N2HET1_0/MIBSPI4CLK/EPWM2B: J16.1 ; port N2HET1_0/MIBSPI4CLK/EPWM2B
N2HET1_1/MIBSPI4NENA/N2HET2_8/EQEP2A: J18.9 ; port N2HET1_1/MIBSPI4NENA/N2HET2_8/EQEP2A
N2HET1_2/MIBSPI4SIMO/EPWM3A: J16.3 ; port N2HET1_2/MIBSPI4SIMO/EPWM3A
N2HET1_3/MIBSPI4NCS_0/N2HET2_10/EQEP2B: J18.11 ; port N2HET1_3/MIBSPI4NCS_0/N2HET2_10/EQEP2B
N2HET1_4/MIBSPI4NCS_1/EPWM4B: J16.5 ; port N2HET1_4/MIBSPI4NCS_1/EPWM4B
N2HET1_6/SCI3RX/EPWM5A: J16.7 ; port N2HET1_6/SCI3RX/EPWM5A
N2HET1_8/MIBSPI1SIMO_1/MII_TXD_3: J16.9 ; port N2HET1_8/MIBSPI1SIMO_1/MII_TXD_3
N2HET1_10/MIBSPI4NCS_4/MII_TXCLK/MII_TX_AVCLK4/NTZ1_3: J16.11 ; port N2HET1_10/MIBSPI4NCS_4/MII_TXCLK/MII_TX_AVCLK4/NTZ1_3
N2HET1_12/MIBSPI4NCS_5/MII_CRS/RMII_CRS_DV: J16.13 ; port N2HET1_12/MIBSPI4NCS_5/MII_CRS/RMII_CRS_DV
N2HET1_14: J16.15 ; port N2HET1_14
N2HET2_1/N2HET1_NDIS: J17.1 ; port N2HET2_1/N2HET1_NDIS
N2HET2_2/N2HET2_NDIS: J19.5 ; port N2HET2_2/N2HET2_NDIS
N2HET2_3/MIBSPI2CLK: J17.3 ; port N2HET2_3/MIBSPI2CLK
N2HET2_5: J17.5 ; port N2HET2_5
N2HET2_6: J19.7 ; port N2HET2_6
N2HET2_7/MIBSPI2NCS_0: J17.7 ; port N2HET2_7/MIBSPI2NCS_0
N2HET2_9: J17.9 ; port N2HET2_9
N2HET2_10: J19.9 ; port N2HET2_10
N2HET2_11: J17.11 ; port N2HET2_11
N2HET2_12/MIBSPI2NENA/MIBSPI2NCS_1: J18.13 ; port N2HET2_12/MIBSPI2NENA/MIBSPI2NCS_1
N2HET2_13/MIBSPI2SOMI: J17.13 ; port N2HET2_13/MIBSPI2SOMI
N2HET2_14/MIBSPI2SIMO: J18.15 ; port N2HET2_14/MIBSPI2SIMO
N2HET2_15: J17.15 ; port N2HET2_15
N2HET2_17: J19.1 ; port N2HET2_17
N2HET2_19/LIN2RX: J19.3 ; port N2HET2_19/LIN2RX
N2HET2_20/LIN2TX: J19.11 ; port N2HET2_20/LIN2TX
N2HET2_21: J19.13 ; port N2HET2_21
N2HET2_22: J15.5 ; port N2HET2_22

Not connected (* = marked no-connect by the designer): J15 7* 9* 11* 13* 15* 17* 19*; J16 17* 19*; J17 17* 19*; J18 17* 19*; J19 15* 17* 19*

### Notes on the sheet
- (near J16) HET1 PATTERN GEN
- (near J18) HET2 PATTERN GEN
- PATTERN GEN CLOCK & WAIT

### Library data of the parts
J15-J19 = SBH11-PBPC-D10-ST-BK: as J11 on sheet TIDM-HAHSCPTO-Test_LogicAna

## Sheet TIDM-HAHSCPTO-Test_Monitor.SchDoc
size 431 x 279 mm; Date: Not shown in title block; ApprovedBy: Not shown in title block; CheckedBy: Not shown in title block; Author: Not shown in title block; CompanyName: Not shown in title block; Engineer: Not shown in title block; Organization: Not shown in title block; Address1: Not shown in title block; Address2: Not shown in title block; Address3: Not shown in title block; Address4: Not shown in title block; DocumentNumber: 1; Revision: Use project parameter SCH_Rev; SheetNumber: 2; SheetTotal: 3; PageSetup: Record=PageOptions¦CenterHorizontal=True¦CenterVertical=True¦PrintScale=1.00¦XCorrection=1.00¦YCorrection=1.00¦PrintKind=0¦BorderSize=5000000¦LeftOffset=0¦BottomOffset=0¦Orientation=2¦PaperLength=1000¦PaperWidth=1000¦Scale=100¦PaperSource=15¦PrintQuality=600¦MediaType=1¦DitherType=10¦PaperKind=Letter¦PrintScaleMode=1
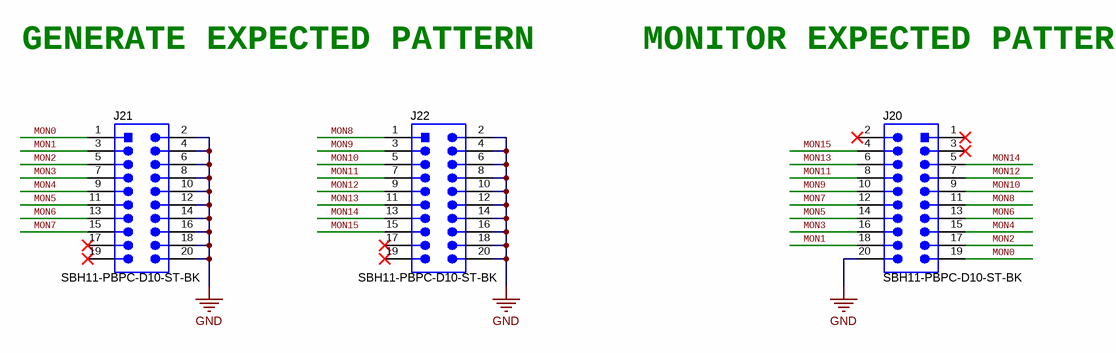
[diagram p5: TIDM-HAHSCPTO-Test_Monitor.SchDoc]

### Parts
J20  SBH11-PBPC-D10-ST-BK  [Sullins_SBH11-xxxC-D10-ST]
J21  SBH11-PBPC-D10-ST-BK  [Sullins_SBH11-xxxC-D10-ST]
J22  SBH11-PBPC-D10-ST-BK  [Sullins_SBH11-xxxC-D10-ST]

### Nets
GND: J20.20 J21.2 J21.4 J21.6 J21.8 J21.10 J21.12 J21.14 J21.16 J21.18 J21.20 J22.2 J22.4 J22.6 J22.8 J22.10 J22.12 J22.14 J22.16 J22.18 J22.20
MON0: J20.19 J21.1
MON1: J20.18 J21.3
MON2: J20.17 J21.5
MON3: J20.16 J21.7
MON4: J20.15 J21.9
MON5: J20.14 J21.11
MON6: J20.13 J21.13
MON7: J20.12 J21.15
MON8: J20.11 J22.1
MON9: J20.10 J22.3
MON10: J20.9 J22.5
MON11: J20.8 J22.7
MON12: J20.7 J22.9
MON13: J20.6 J22.11
MON14: J20.5 J22.13
MON15: J20.4 J22.15

Not connected (* = marked no-connect by the designer): J20 1* 2* 3*; J21 17* 19*; J22 17* 19*

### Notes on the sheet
- GENERATE EXPECTED PATTERN
- MONITOR EXPECTED PATTERN

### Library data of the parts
J20-J22 = SBH11-PBPC-D10-ST-BK: as J11 on sheet TIDM-HAHSCPTO-Test_LogicAna

## Sheet TIDM-HAHSCPTO-Test_Hw.SchDoc
size 431 x 279 mm; Date: Not shown in title block; ApprovedBy: Not shown in title block; CheckedBy: Not shown in title block; Author: Not shown in title block; CompanyName: Not shown in title block; Engineer: Not shown in title block; Organization: Not shown in title block; Address1: Not shown in title block; Address2: Not shown in title block; Address3: Not shown in title block; Address4: Not shown in title block; DocumentNumber: 1; Revision: Use project parameter SCH_Rev; SheetNumber: 3; SheetTotal: 3; PageSetup: Record=PageOptions¦CenterHorizontal=True¦CenterVertical=True¦PrintScale=1.00¦XCorrection=1.00¦YCorrection=1.00¦PrintKind=0¦BorderSize=5000000¦LeftOffset=0¦BottomOffset=0¦Orientation=2¦PaperLength=1000¦PaperWidth=1000¦Scale=100¦PaperSource=15¦PrintQuality=600¦MediaType=1¦DitherType=10¦PaperKind=Letter¦PrintScaleMode=1
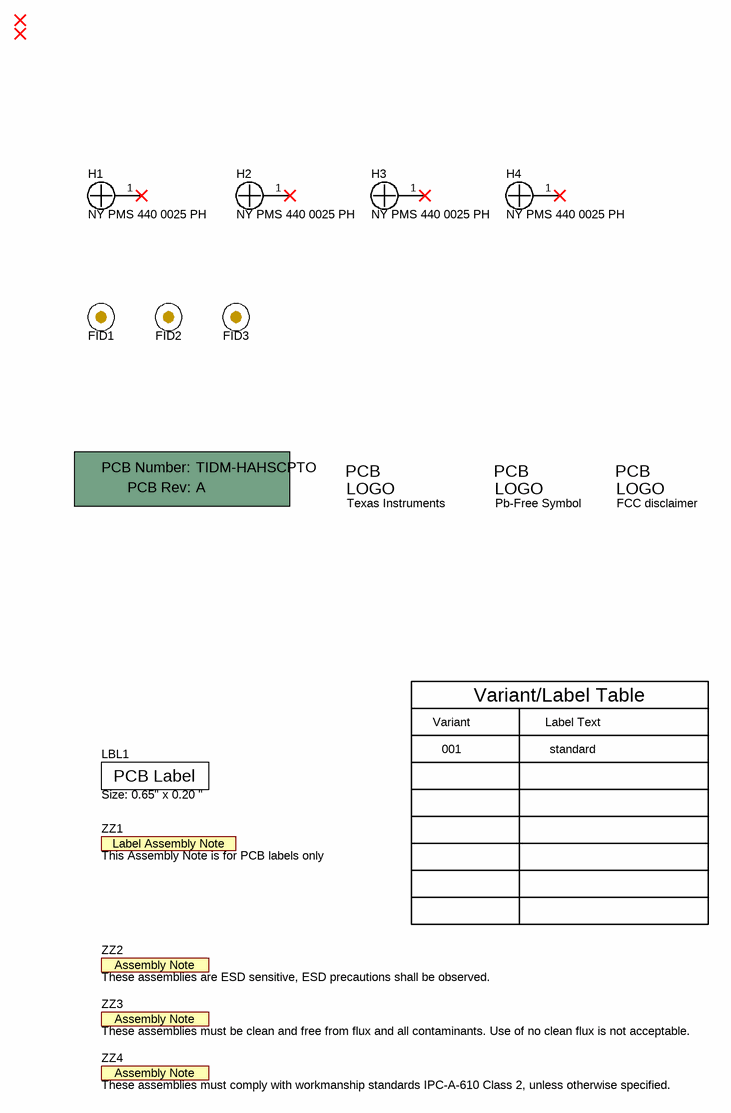
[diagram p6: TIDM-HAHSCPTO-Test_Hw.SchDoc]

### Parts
!PCB  Printed Circuit Board  (value not drawn)  (mechanical)
FID1  Fiducial  [Fiducial10-20]  (value not drawn)
FID2  Fiducial  [Fiducial10-20]  (value not drawn)
FID3  Fiducial  [Fiducial10-20]  (value not drawn)
H1  NY PMS 440 0025 PH  [NY PMS 440 0025 PH]
H2  NY PMS 440 0025 PH  [NY PMS 440 0025 PH]
H3  NY PMS 440 0025 PH  [NY PMS 440 0025 PH]
H4  NY PMS 440 0025 PH  [NY PMS 440 0025 PH]
LBL1  Size: 0.65" x 0.20 "  [Label_650x200]
Logo1  Texas Instruments  [TI_Stacked_Overlay_Small]  (no BOM)
Logo2  Pb-Free Symbol  [Pb-Free_Overlay_Small]  (no BOM)
Logo3  FCC disclaimer  [FCC_disclaimer]  (no BOM)
ZZ1  This Assembly Note is for PCB labels only  [AssemblyNoteLabel]  (no BOM)
ZZ2  These assemblies are ESD sensitive, ESD precautions shall be observed.  [AssemblyNote]  (no BOM)
ZZ3  These assemblies must be clean and free from flux and all contaminants. Use of no clean flux is not acceptable.  [AssemblyNote]  (no BOM)
ZZ4  These assemblies must comply with workmanship standards IPC-A-610 Class 2, unless otherwise specified.  [AssemblyNote]  (no BOM)

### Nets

Not connected (* = marked no-connect by the designer): H1 1*; H2 1*; H3 1*; H4 1*

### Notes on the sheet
- Variant
- Variant/Label Table
- Label Text
- 001
- standard

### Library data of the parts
!PCB = PCB: Manufacturer: Any; PartNumber: TIDM-HAHSCPTO; SymbolCreator: a0412235
FID1-FID3 = Fiducial: Fiducial mark.  There is nothing to buy or mount.; SymbolCreator: codlsc
H1-H4 = NY PMS 440 0025 PH: Machine Screw, Round, #4-40 x 1/4, Nylon, Philips panhead; Manufacturer: B&F Fastener Supply; CompType: Hardware; SymbolCreator: codlsc; U/M: EA
LBL1 = THT-14-423-10: Thermal Transfer Printable Labels, 0.650" W x 0.200" H - 10,000 per roll; Manufacturer: Brady; SymbolCreator: a0412235; CompType: Label
Logo1 = TI_Logo: Texas Instrument Corporate Signature; SymbolCreator: codlsc
Logo2 = Pb-Free: SymbolCreator: a0412235
Logo3 = FCC_disclaimer: SymbolCreator: codlsc
ZZ1 = AssemblyNoteLabel: SymbolCreator: a0412235
ZZ2-ZZ4 = AssemblyNote: SymbolCreator: codlsc

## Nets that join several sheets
GND: TIDM-HAHSCPTO-Test_BoosterPack (J2.1 J3.2 J6.1 J7.2), TIDM-HAHSCPTO-Test_Proto (10 pins), TIDM-HAHSCPTO-Test_LogicAna (J11.20 J12.20 J13.20 J14.20), TIDM-HAHSCPTO-Test_PatGen (50 pins), TIDM-HAHSCPTO-Test_Monitor (21 pins)
+3V3: TIDM-HAHSCPTO-Test_BoosterPack (J1.1 J5.1), TIDM-HAHSCPTO-Test_Proto (J9.3 J10.3)
+5V: TIDM-HAHSCPTO-Test_BoosterPack (J3.1 J7.1), TIDM-HAHSCPTO-Test_Proto (J9.1 J10.1)
ECLK1T: TIDM-HAHSCPTO-Test_Proto (J9.19), TIDM-HAHSCPTO-Test_PatGen (J15.1)
GIOA_0: TIDM-HAHSCPTO-Test_BoosterPack (J4.10), TIDM-HAHSCPTO-Test_Proto (J10.7)
GIOA_2/N2HET2_0/EQEP2I: TIDM-HAHSCPTO-Test_BoosterPack (J4.8), TIDM-HAHSCPTO-Test_LogicAna (J13.19), TIDM-HAHSCPTO-Test_PatGen (J18.1)
GIOA_3/N2HET2_2: TIDM-HAHSCPTO-Test_Proto (J10.18), TIDM-HAHSCPTO-Test_LogicAna (J13.17), TIDM-HAHSCPTO-Test_PatGen (J18.3)
GIOA_6/N2HET2_4/EPWM1B: TIDM-HAHSCPTO-Test_BoosterPack (J1.8), TIDM-HAHSCPTO-Test_LogicAna (J13.15), TIDM-HAHSCPTO-Test_PatGen (J18.5)
GIOA_7/N2HET2_6/EPWM2A: TIDM-HAHSCPTO-Test_BoosterPack (J1.5), TIDM-HAHSCPTO-Test_LogicAna (J13.13), TIDM-HAHSCPTO-Test_PatGen (J18.7)
GIOB_2/DCAN4TX: TIDM-HAHSCPTO-Test_BoosterPack (J2.10), TIDM-HAHSCPTO-Test_Proto (J10.5)
GIOB_3/DCAN4RX: TIDM-HAHSCPTO-Test_BoosterPack (J2.4), TIDM-HAHSCPTO-Test_Proto (J10.6)
HERCULES_NRST: TIDM-HAHSCPTO-Test_BoosterPack (J2.5 J6.5), TIDM-HAHSCPTO-Test_Proto (J10.41)
MIBSPI1NCS_1/MII_COL/N2HET1_17/EQEP1S: TIDM-HAHSCPTO-Test_BoosterPack (J6.8), TIDM-HAHSCPTO-Test_LogicAna (J12.18)
MIBSPI1NCS_2/MDIO/N2HET1_19: TIDM-HAHSCPTO-Test_BoosterPack (J6.9), TIDM-HAHSCPTO-Test_LogicAna (J12.16)
MIBSPI1NCS_3/N2HET1_21/NTZ1_3: TIDM-HAHSCPTO-Test_Proto (J10.27), TIDM-HAHSCPTO-Test_LogicAna (J12.14)
MIBSPI1NENA/MII_RXD_2/N2HET1_23/ECAP4: TIDM-HAHSCPTO-Test_BoosterPack (J8.4), TIDM-HAHSCPTO-Test_LogicAna (J12.12)
MIBSPI3NCS_1/MDCLK/N2HET1_25: TIDM-HAHSCPTO-Test_BoosterPack (J2.3), TIDM-HAHSCPTO-Test_LogicAna (J12.10)
MIBSPI3NCS_2/I2C1_SDA/N2HET1_27/NTZ1_2: TIDM-HAHSCPTO-Test_BoosterPack (J2.8), TIDM-HAHSCPTO-Test_LogicAna (J12.8)
MIBSPI3NCS_3/I2C1_SCL/N2HET1_29/NTZ1_1: TIDM-HAHSCPTO-Test_BoosterPack (J2.9), TIDM-HAHSCPTO-Test_LogicAna (J12.2), TIDM-HAHSCPTO-Test_PatGen (J15.3)
N2HET1_0/MIBSPI4CLK/EPWM2B: TIDM-HAHSCPTO-Test_Proto (J10.20), TIDM-HAHSCPTO-Test_LogicAna (J11.19), TIDM-HAHSCPTO-Test_PatGen (J16.1)
N2HET1_1/MIBSPI4NENA/N2HET2_8/EQEP2A: TIDM-HAHSCPTO-Test_BoosterPack (J6.2), TIDM-HAHSCPTO-Test_Proto (J10.21), TIDM-HAHSCPTO-Test_LogicAna (J11.18 J13.11), TIDM-HAHSCPTO-Test_PatGen (J18.9)
N2HET1_2/MIBSPI4SIMO/EPWM3A: TIDM-HAHSCPTO-Test_BoosterPack (J4.1), TIDM-HAHSCPTO-Test_LogicAna (J11.17), TIDM-HAHSCPTO-Test_PatGen (J16.3)
N2HET1_3/MIBSPI4NCS_0/N2HET2_10/EQEP2B: TIDM-HAHSCPTO-Test_Proto (J10.22), TIDM-HAHSCPTO-Test_LogicAna (J11.16 J13.9), TIDM-HAHSCPTO-Test_PatGen (J18.11)
N2HET1_4/MIBSPI4NCS_1/EPWM4B: TIDM-HAHSCPTO-Test_BoosterPack (J1.9), TIDM-HAHSCPTO-Test_LogicAna (J11.15), TIDM-HAHSCPTO-Test_PatGen (J16.5)
N2HET1_5/MIBSPI4SOMI/N2HET2_12/EPWM3B: TIDM-HAHSCPTO-Test_Proto (J10.25), TIDM-HAHSCPTO-Test_LogicAna (J11.14)
N2HET1_6/SCI3RX/EPWM5A: TIDM-HAHSCPTO-Test_BoosterPack (J1.3), TIDM-HAHSCPTO-Test_LogicAna (J11.13), TIDM-HAHSCPTO-Test_PatGen (J16.7)
N2HET1_7/MIBSPI4NCS_2/N2HET2_14/EPWM7B: TIDM-HAHSCPTO-Test_Proto (J10.28), TIDM-HAHSCPTO-Test_LogicAna (J11.12)
N2HET1_8/MIBSPI1SIMO_1/MII_TXD_3: TIDM-HAHSCPTO-Test_BoosterPack (J8.3), TIDM-HAHSCPTO-Test_LogicAna (J11.11), TIDM-HAHSCPTO-Test_PatGen (J16.9)
N2HET1_9/MIBSPI4NCS_3/N2HET2_16/EPWM7A: TIDM-HAHSCPTO-Test_BoosterPack (J1.10), TIDM-HAHSCPTO-Test_LogicAna (J11.10 J14.19)
N2HET1_10/MIBSPI4NCS_4/MII_TXCLK/MII_TX_AVCLK4/NTZ1_3: TIDM-HAHSCPTO-Test_BoosterPack (J8.1), TIDM-HAHSCPTO-Test_LogicAna (J11.9), TIDM-HAHSCPTO-Test_PatGen (J16.11)
N2HET1_12/MIBSPI4NCS_5/MII_CRS/RMII_CRS_DV: TIDM-HAHSCPTO-Test_BoosterPack (J4.6), TIDM-HAHSCPTO-Test_LogicAna (J11.7), TIDM-HAHSCPTO-Test_PatGen (J16.13)
N2HET1_13/SCI3TX/N2HET2_20/EPWM5B: TIDM-HAHSCPTO-Test_BoosterPack (J1.4), TIDM-HAHSCPTO-Test_LogicAna (J11.6 J14.15)
N2HET1_14: TIDM-HAHSCPTO-Test_BoosterPack (J4.5), TIDM-HAHSCPTO-Test_LogicAna (J11.5), TIDM-HAHSCPTO-Test_PatGen (J16.15)
N2HET1_16/EPWM1SYNCI/EPWM1SYNCO: TIDM-HAHSCPTO-Test_BoosterPack (J4.3), TIDM-HAHSCPTO-Test_LogicAna (J12.19)
N2HET1_18/EMIF_RNW/EPWM6A: TIDM-HAHSCPTO-Test_BoosterPack (J4.2), TIDM-HAHSCPTO-Test_LogicAna (J12.17)
N2HET1_21/EMIF_NDQM_2: TIDM-HAHSCPTO-Test_Proto (J10.24), TIDM-HAHSCPTO-Test_LogicAna (J14.14)
N2HET1_22/EMIF_NDQM_3: TIDM-HAHSCPTO-Test_BoosterPack (J2.2), TIDM-HAHSCPTO-Test_LogicAna (J12.13)
N2HET1_23/EMIF_BA_0: TIDM-HAHSCPTO-Test_Proto (J10.12), TIDM-HAHSCPTO-Test_LogicAna (J11.2)
N2HET1_24/MIBSPI1NCS_5/MII_RXD_0/RMII_RXD_0: TIDM-HAHSCPTO-Test_BoosterPack (J5.9), TIDM-HAHSCPTO-Test_LogicAna (J12.11)
N2HET1_26/MII_RXD_1/RMII_RXD_1: TIDM-HAHSCPTO-Test_BoosterPack (J5.10), TIDM-HAHSCPTO-Test_LogicAna (J12.9)
N2HET1_27: TIDM-HAHSCPTO-Test_Proto (J9.8), TIDM-HAHSCPTO-Test_LogicAna (J12.3)
N2HET1_28/MII_RXCLK/RMII_REFCLK/MII_RX_AVCLK4: TIDM-HAHSCPTO-Test_BoosterPack (J8.2), TIDM-HAHSCPTO-Test_LogicAna (J12.7)
N2HET1_29: TIDM-HAHSCPTO-Test_Proto (J10.11), TIDM-HAHSCPTO-Test_LogicAna (J12.6)
N2HET1_30/MII_RX_DV/EQEP2S: TIDM-HAHSCPTO-Test_BoosterPack (J4.4), TIDM-HAHSCPTO-Test_LogicAna (J12.5)
N2HET1_31: TIDM-HAHSCPTO-Test_Proto (J10.10), TIDM-HAHSCPTO-Test_LogicAna (J11.3)
N2HET2_0: TIDM-HAHSCPTO-Test_Proto (J9.5), TIDM-HAHSCPTO-Test_LogicAna (J14.11)
N2HET2_1/N2HET1_NDIS: TIDM-HAHSCPTO-Test_Proto (J9.6), TIDM-HAHSCPTO-Test_LogicAna (J13.18), TIDM-HAHSCPTO-Test_PatGen (J17.1)
N2HET2_2/N2HET2_NDIS: TIDM-HAHSCPTO-Test_Proto (J9.18), TIDM-HAHSCPTO-Test_LogicAna (J14.10), TIDM-HAHSCPTO-Test_PatGen (J19.5)
N2HET2_3/MIBSPI2CLK: TIDM-HAHSCPTO-Test_Proto (J9.17), TIDM-HAHSCPTO-Test_LogicAna (J13.16), TIDM-HAHSCPTO-Test_PatGen (J17.3)
N2HET2_4: TIDM-HAHSCPTO-Test_Proto (J9.14), TIDM-HAHSCPTO-Test_LogicAna (J14.9)
N2HET2_5: TIDM-HAHSCPTO-Test_Proto (J9.11), TIDM-HAHSCPTO-Test_LogicAna (J13.14), TIDM-HAHSCPTO-Test_PatGen (J17.5)
N2HET2_6: TIDM-HAHSCPTO-Test_Proto (J9.7), TIDM-HAHSCPTO-Test_LogicAna (J14.8), TIDM-HAHSCPTO-Test_PatGen (J19.7)
N2HET2_7/MIBSPI2NCS_0: TIDM-HAHSCPTO-Test_Proto (J9.20), TIDM-HAHSCPTO-Test_LogicAna (J13.12), TIDM-HAHSCPTO-Test_PatGen (J17.7)
N2HET2_8: TIDM-HAHSCPTO-Test_Proto (J10.19), TIDM-HAHSCPTO-Test_LogicAna (J14.7)
N2HET2_9: TIDM-HAHSCPTO-Test_Proto (J9.27), TIDM-HAHSCPTO-Test_LogicAna (J13.10), TIDM-HAHSCPTO-Test_PatGen (J17.9)
N2HET2_10: TIDM-HAHSCPTO-Test_Proto (J9.26), TIDM-HAHSCPTO-Test_LogicAna (J14.6), TIDM-HAHSCPTO-Test_PatGen (J19.9)
N2HET2_11: TIDM-HAHSCPTO-Test_Proto (J9.24), TIDM-HAHSCPTO-Test_LogicAna (J13.8), TIDM-HAHSCPTO-Test_PatGen (J17.11)
N2HET2_12/MIBSPI2NENA/MIBSPI2NCS_1: TIDM-HAHSCPTO-Test_Proto (J10.47), TIDM-HAHSCPTO-Test_LogicAna (J13.7), TIDM-HAHSCPTO-Test_PatGen (J18.13)
N2HET2_13/MIBSPI2SOMI: TIDM-HAHSCPTO-Test_Proto (J10.46), TIDM-HAHSCPTO-Test_LogicAna (J13.6), TIDM-HAHSCPTO-Test_PatGen (J17.13)
N2HET2_14/MIBSPI2SIMO: TIDM-HAHSCPTO-Test_Proto (J9.22), TIDM-HAHSCPTO-Test_LogicAna (J13.5), TIDM-HAHSCPTO-Test_PatGen (J18.15)
N2HET2_15: TIDM-HAHSCPTO-Test_Proto (J10.33), TIDM-HAHSCPTO-Test_LogicAna (J13.4), TIDM-HAHSCPTO-Test_PatGen (J17.15)
N2HET2_16: TIDM-HAHSCPTO-Test_Proto (J10.29), TIDM-HAHSCPTO-Test_LogicAna (J14.5)
N2HET2_17: TIDM-HAHSCPTO-Test_Proto (J10.34), TIDM-HAHSCPTO-Test_LogicAna (J14.18), TIDM-HAHSCPTO-Test_PatGen (J19.1)
N2HET2_18: TIDM-HAHSCPTO-Test_Proto (J10.43), TIDM-HAHSCPTO-Test_LogicAna (J14.17)
N2HET2_19/LIN2RX: TIDM-HAHSCPTO-Test_Proto (J9.10), TIDM-HAHSCPTO-Test_LogicAna (J14.16), TIDM-HAHSCPTO-Test_PatGen (J19.3)
N2HET2_20/LIN2TX: TIDM-HAHSCPTO-Test_Proto (J9.9), TIDM-HAHSCPTO-Test_LogicAna (J14.3), TIDM-HAHSCPTO-Test_PatGen (J19.11)
N2HET2_21: TIDM-HAHSCPTO-Test_Proto (J10.42), TIDM-HAHSCPTO-Test_LogicAna (J14.4), TIDM-HAHSCPTO-Test_PatGen (J19.13)
N2HET2_22: TIDM-HAHSCPTO-Test_Proto (J9.28), TIDM-HAHSCPTO-Test_LogicAna (J14.13), TIDM-HAHSCPTO-Test_PatGen (J15.5)
N2HET2_23: TIDM-HAHSCPTO-Test_Proto (J9.23), TIDM-HAHSCPTO-Test_LogicAna (J14.12)

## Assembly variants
001: not fitted FID3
